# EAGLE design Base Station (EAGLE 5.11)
OC_FARNELL: 1741293

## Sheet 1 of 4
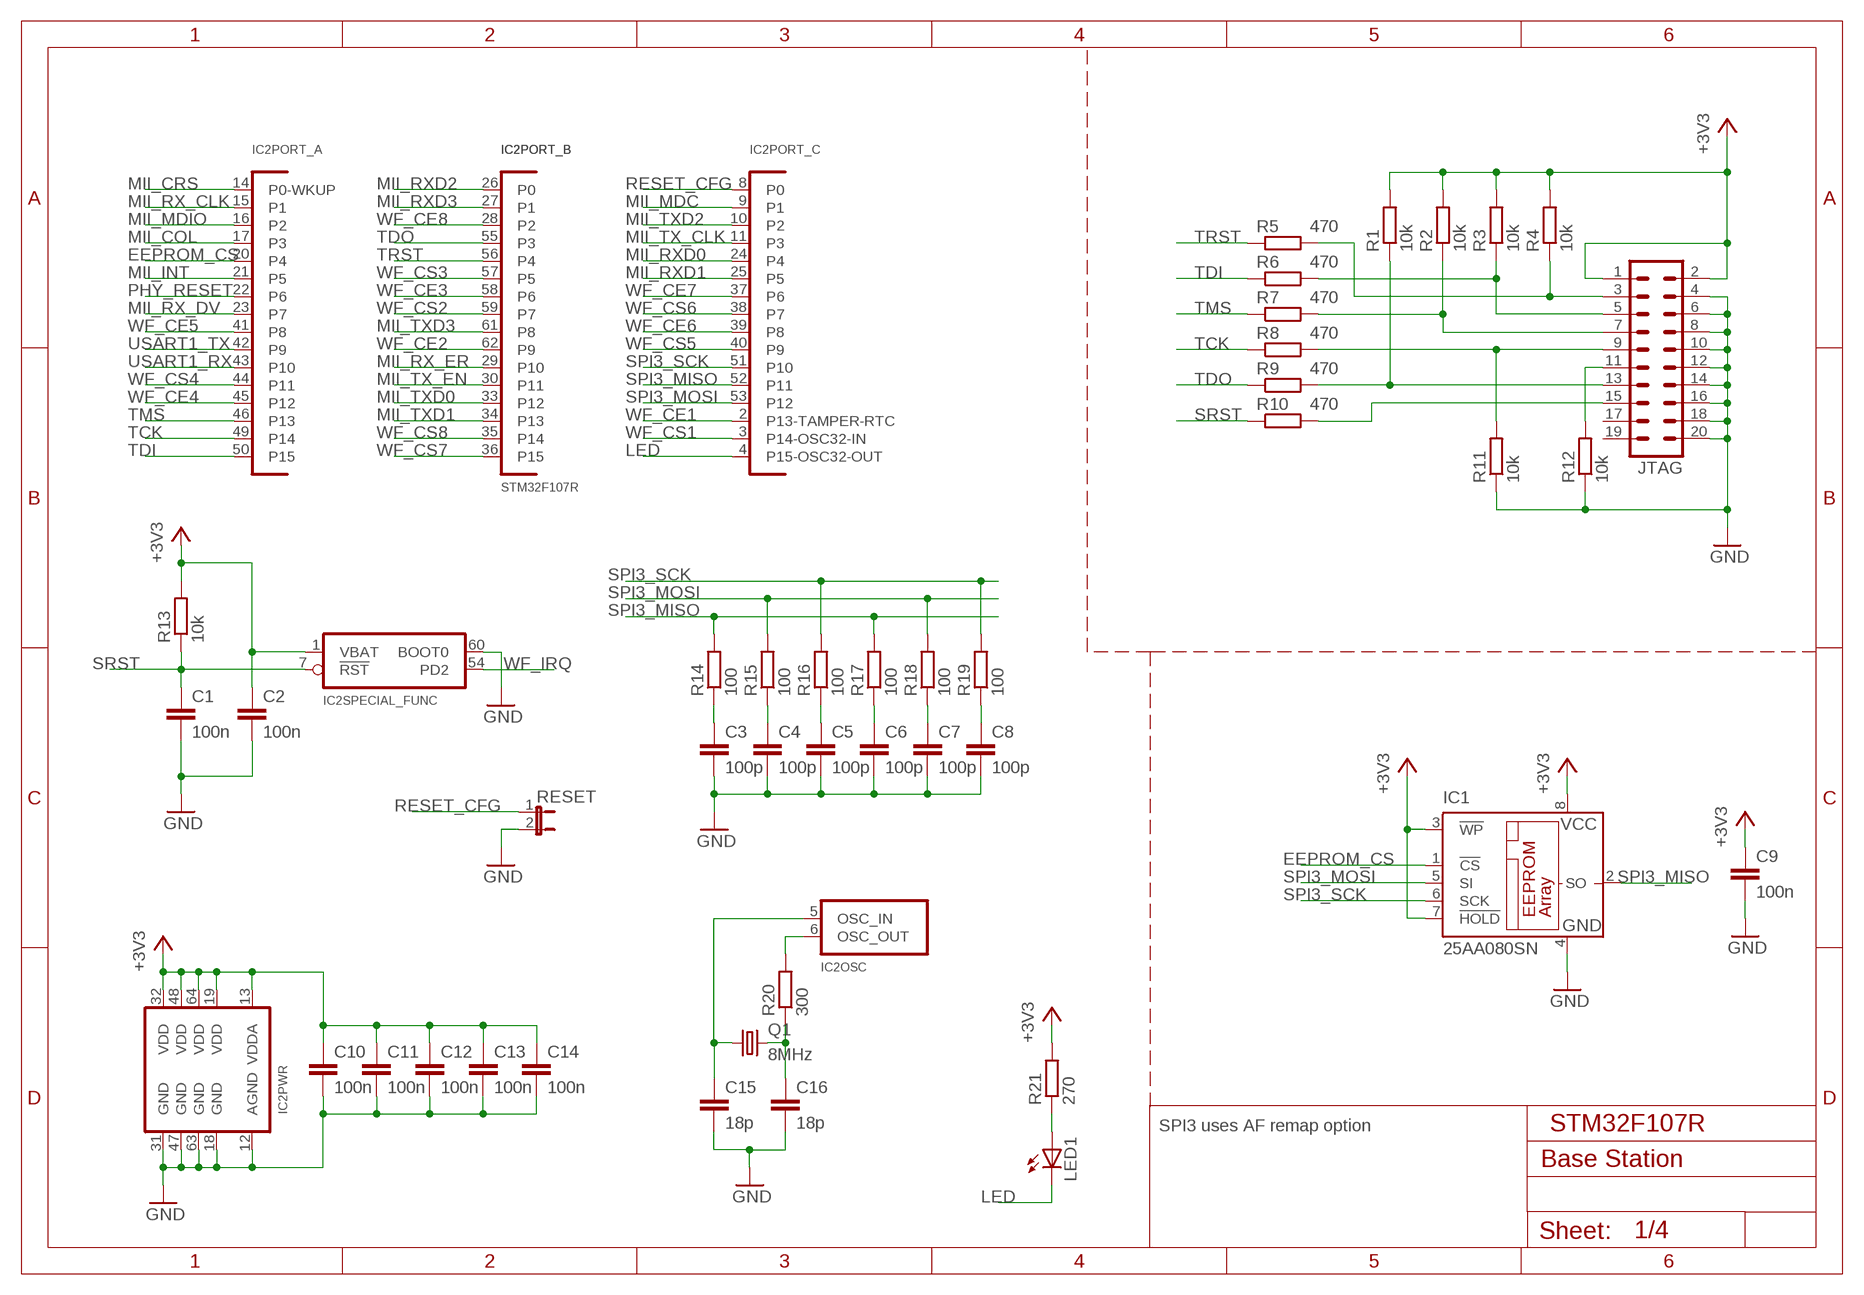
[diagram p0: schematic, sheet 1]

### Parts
C1  100n  C-EUC0805  [C0805]
C2  100n  C-EUC0805  [C0805]
C3  100p  C-EUC0805  [C0805]
C4  100p  C-EUC0805  [C0805]
C5  100p  C-EUC0805  [C0805]
C6  100p  C-EUC0805  [C0805]
C7  100p  C-EUC0805  [C0805]
C8  100p  C-EUC0805  [C0805]
C9  100n  C-EUC0805  [C0805]
C10  100n  C-EUC0805  [C0805]
C11  100n  C-EUC0805  [C0805]
C12  100n  C-EUC0805  [C0805]
C13  100n  C-EUC0805  [C0805]
C14  100n  C-EUC0805  [C0805]
C15  18p  C-EUC0805  [C0805]
C16  18p  C-EUC0805  [C0805]
IC1  25AA080SN  [SO-08]
IC2  STM32F107R  [LQFP64]
JTAG  ML20  [ML20]
LED1  LEDCHIP-LED0805  [CHIP-LED0805]
Q1  8MHz  CRYSTAL7A  [CRYSTAL-7A]
R1  10k  R-EU_R0805  [R0805]
R2  10k  R-EU_R0805  [R0805]
R3  10k  R-EU_R0805  [R0805]
R4  10k  R-EU_R0805  [R0805]
R5  470  R-EU_R0805  [R0805]
R6  470  R-EU_R0805  [R0805]
R7  470  R-EU_R0805  [R0805]
R8  470  R-EU_R0805  [R0805]
R9  470  R-EU_R0805  [R0805]
R10  470  R-EU_R0805  [R0805]
R11  10k  R-EU_R0805  [R0805]
R12  10k  R-EU_R0805  [R0805]
R13  10k  R-EU_R0805  [R0805]
R14  100  R-EU_R0805  [R0805]
R15  100  R-EU_R0805  [R0805]
R16  100  R-EU_R0805  [R0805]
R17  100  R-EU_R0805  [R0805]
R18  100  R-EU_R0805  [R0805]
R19  100  R-EU_R0805  [R0805]
R20  300  R-EU_R0805  [R0805]
R21  270  R-EU_R0805  [R0805]
RESET  JP1E  [JP1]

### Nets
+3V3: C2.1 C9.1 C10.1 C11.1 C12.1 C13.1 C14.1 IC1.3(!WP) IC1.7(!HOLD) IC1.8(VCC) IC2.1(SPECIAL_FUNC:VBAT) IC2.13(PWR:VDDA) IC2.19(PWR:VDD) IC2.32(PWR:VDD) IC2.48(PWR:VDD) IC2.64(PWR:VDD) JTAG.1 JTAG.2 R1.2 R2.2 R3.2 R4.2 R13.2 R21.2 ; also sheet 2,3,4
EEPROM_CS: IC1.1(!CS) IC2.20(PORT_A:P4)
GND: C1.2 C2.2 C3.2 C4.2 C5.2 C6.2 C7.2 C8.2 C9.2 C10.2 C11.2 C12.2 C13.2 C14.2 C15.2 C16.2 IC1.4(GND) IC2.12(PWR:AGND) IC2.18(PWR:GND) IC2.31(PWR:GND) IC2.47(PWR:GND) IC2.60(SPECIAL_FUNC:BOOT0) IC2.63(PWR:GND) JTAG.4 JTAG.6 JTAG.8 JTAG.10 JTAG.12 JTAG.14 JTAG.16 JTAG.18 JTAG.20 R11.1 R12.1 RESET.2 ; also sheet 2,3,4
JTAG-SRST: JTAG.15 R10.2
JTAG-TCK: JTAG.9 R8.2 R11.2
JTAG-TDI: JTAG.5 R3.1 R6.2
JTAG-TDO: JTAG.13 R1.1 R9.2
JTAG-TMS: JTAG.7 R2.1 R7.2
JTAG-TRST: JTAG.3 R4.1 R5.2
LED: IC2.4(PORT_C:P15-OSC32-OUT) LED1.C
MII_COL: IC2.17(PORT_A:P3) ; also sheet 2
MII_CRS: IC2.14(PORT_A:P0-WKUP) ; also sheet 2
MII_INT: IC2.21(PORT_A:P5) ; also sheet 2
MII_MDC: IC2.9(PORT_C:P1) ; also sheet 2
MII_MDIO: IC2.16(PORT_A:P2) ; also sheet 2
MII_RX_CLK: IC2.15(PORT_A:P1) ; also sheet 2
MII_RX_DV: IC2.23(PORT_A:P7) ; also sheet 2
MII_RX_ER: IC2.29(PORT_B:P10) ; also sheet 2
MII_RXD0: IC2.24(PORT_C:P4) ; also sheet 2
MII_RXD1: IC2.25(PORT_C:P5) ; also sheet 2
MII_RXD2: IC2.26(PORT_B:P0) ; also sheet 2
MII_RXD3: IC2.27(PORT_B:P1) ; also sheet 2
MII_TX_CLK: IC2.11(PORT_C:P3) ; also sheet 2
MII_TX_EN: IC2.30(PORT_B:P11) ; also sheet 2
MII_TXD0: IC2.33(PORT_B:P12) ; also sheet 2
MII_TXD1: IC2.34(PORT_B:P13) ; also sheet 2
MII_TXD2: IC2.10(PORT_C:P2) ; also sheet 2
MII_TXD3: IC2.61(PORT_B:P8) ; also sheet 2
N$17: C3.1 R14.1
N$19: C4.1 R15.1
N$57: LED1.A R21.1
N$58: C5.1 R16.1
N$59: C6.1 R17.1
N$60: C7.1 R18.1
N$61: C8.1 R19.1
N$165: IC2.6(OSC:OSC_OUT) R20.2
N$168: C15.1 IC2.5(OSC:OSC_IN) Q1.1
N$169: C16.1 Q1.2 R20.1
N$173: JTAG.11 R12.2
PHY_RESET: IC2.22(PORT_A:P6) ; also sheet 2
RESET_CFG: IC2.8(PORT_C:P0) RESET.1
SPI3_MISO: IC1.2(SO) IC2.52(PORT_C:P11) R14.2 R17.2 ; also sheet 3
SPI3_MOSI: IC1.5(SI) IC2.53(PORT_C:P12) R15.2 R18.2 ; also sheet 3
SPI3_SCK: IC1.6(SCK) IC2.51(PORT_C:P10) R16.2 R19.2 ; also sheet 3
SRST: C1.1 IC2.7(SPECIAL_FUNC:!RST) R10.1 R13.1
TCK: IC2.49(PORT_A:P14) R8.1
TDI: IC2.50(PORT_A:P15) R6.1
TDO: IC2.55(PORT_B:P3) R9.1
TMS: IC2.46(PORT_A:P13) R7.1
TRST: IC2.56(PORT_B:P4) R5.1
USART1_RX: IC2.43(PORT_A:P10) ; also sheet 4
USART1_TX: IC2.42(PORT_A:P9) ; also sheet 4
WF_CE1: IC2.2(PORT_C:P13-TAMPER-RTC) ; also sheet 3
WF_CE2: IC2.62(PORT_B:P9) ; also sheet 3
WF_CE3: IC2.58(PORT_B:P6) ; also sheet 3
WF_CE4: IC2.45(PORT_A:P12) ; also sheet 3
WF_CE5: IC2.41(PORT_A:P8) ; also sheet 3
WF_CE6: IC2.39(PORT_C:P8) ; also sheet 3
WF_CE7: IC2.37(PORT_C:P6) ; also sheet 3
WF_CE8: IC2.28(PORT_B:P2) ; also sheet 3
WF_CS1: IC2.3(PORT_C:P14-OSC32-IN) ; also sheet 3
WF_CS2: IC2.59(PORT_B:P7) ; also sheet 3
WF_CS3: IC2.57(PORT_B:P5) ; also sheet 3
WF_CS4: IC2.44(PORT_A:P11) ; also sheet 3
WF_CS5: IC2.40(PORT_C:P9) ; also sheet 3
WF_CS6: IC2.38(PORT_C:P7) ; also sheet 3
WF_CS7: IC2.36(PORT_B:P15) ; also sheet 3
WF_CS8: IC2.35(PORT_B:P14) ; also sheet 3
WF_IRQ: IC2.54(SPECIAL_FUNC:PD2) ; also sheet 3
Unconnected: JTAG.17 JTAG.19

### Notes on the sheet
- SPI3 uses AF remap option | STM32F107R

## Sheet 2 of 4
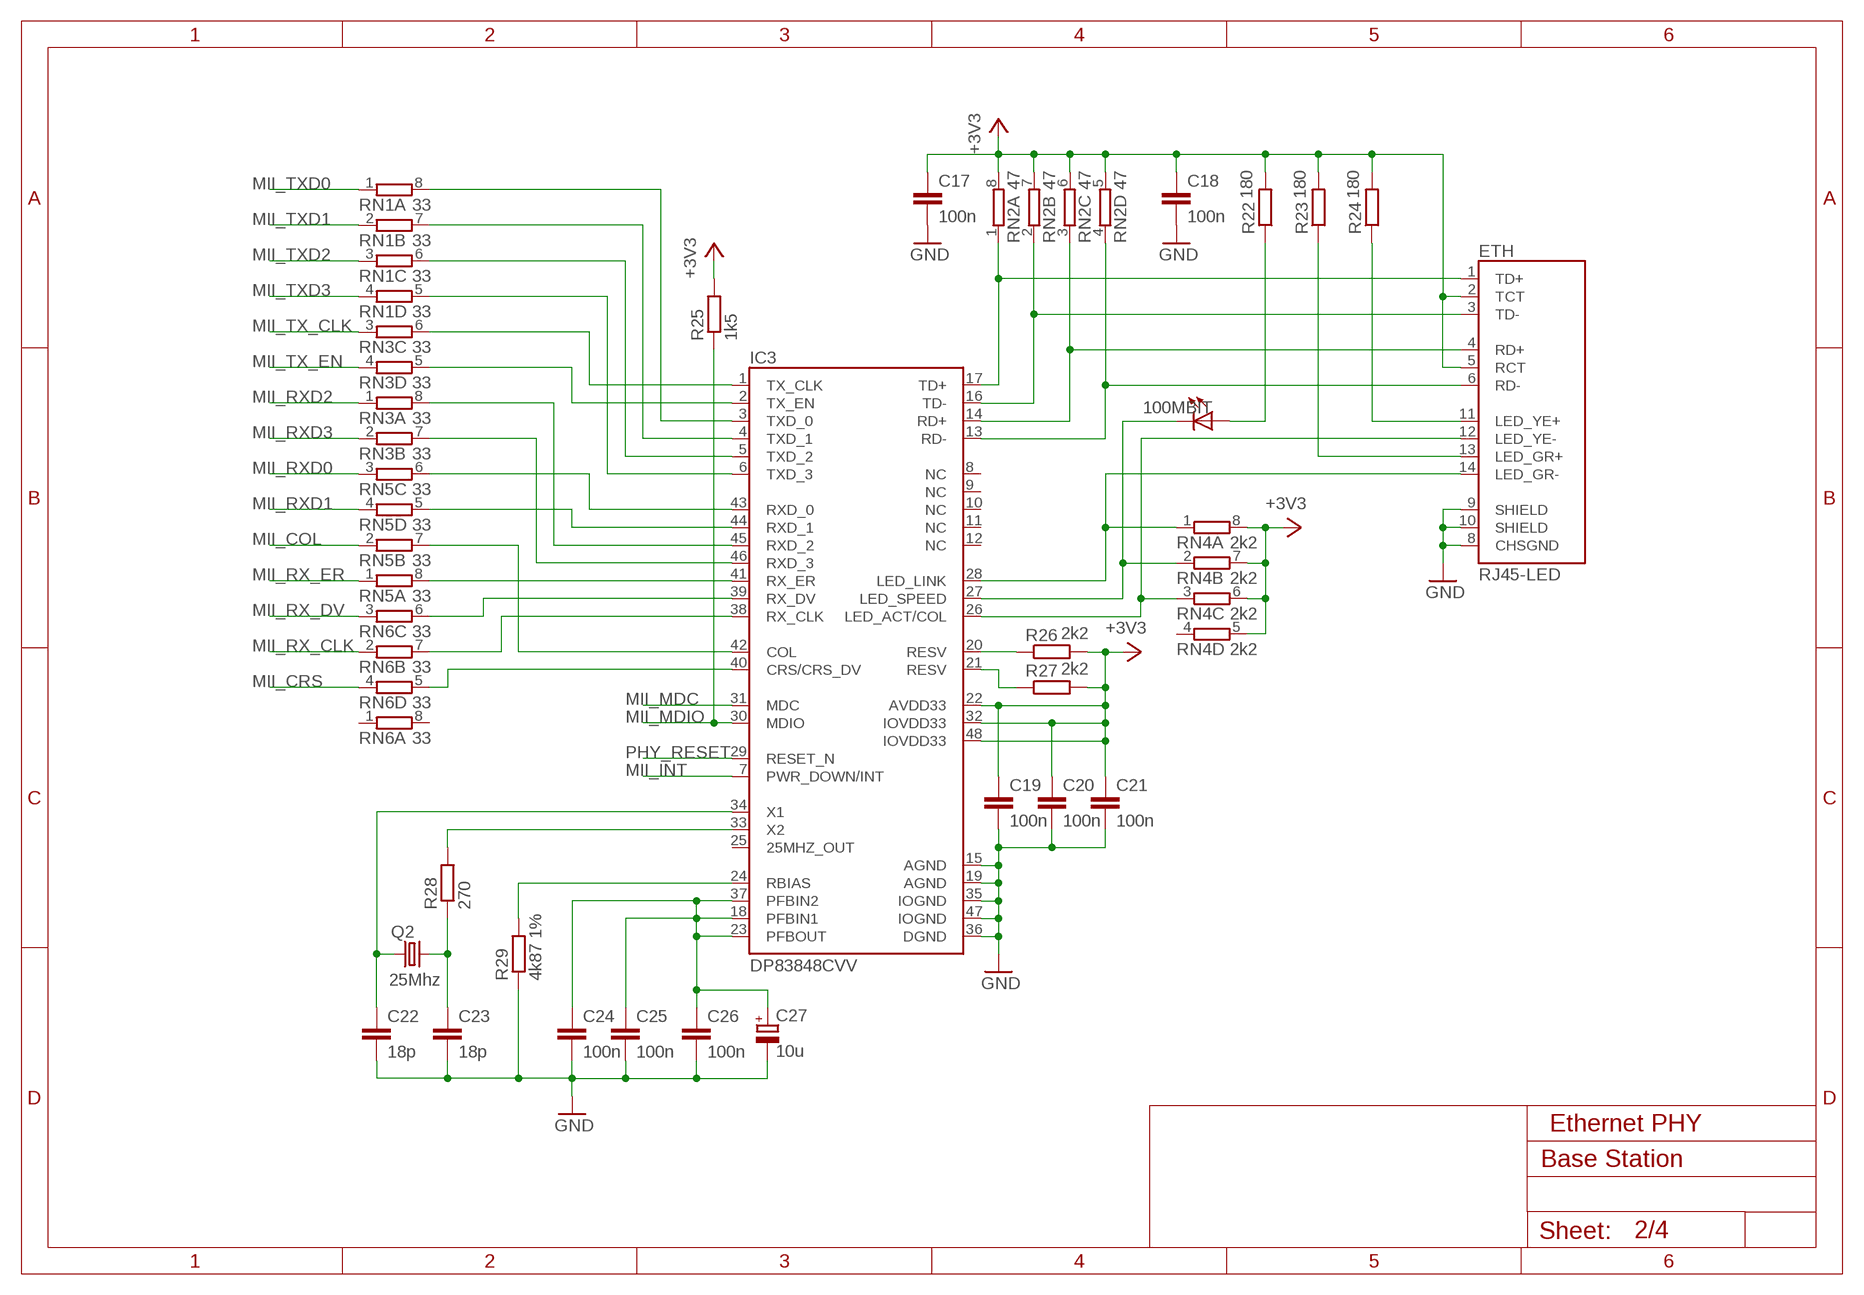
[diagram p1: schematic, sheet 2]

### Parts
100MBIT  LEDCHIP-LED0805  [CHIP-LED0805]
C17  100n  C-EUC0805  [C0805]
C18  100n  C-EUC0805  [C0805]
C19  100n  C-EUC0805  [C0805]
C20  100n  C-EUC0805  [C0805]
C21  100n  C-EUC0805  [C0805]
C22  18p  C-EUC0805  [C0805]
C23  18p  C-EUC0805  [C0805]
C24  100n  C-EUC0805  [C0805]
C25  100n  C-EUC0805  [C0805]
C26  100n  C-EUC0805  [C0805]
C27  10u  CPOL-EUC/6032-28R  [C/6032-28R]
ETH  RJ45-LED  [RJ45-LED]
IC3  DP83848CVV  DB8348C  [LQFP48]
Q2  25Mhz  CRYSTALCTS406  [CTS406]
R22  180  R-EU_R0805  [R0805]
R23  180  R-EU_R0805  [R0805]
R24  180  R-EU_R0805  [R0805]
R25  1k5  R-EU_R0805  [R0805]
R26  2k2  R-EU_R0805  [R0805]
R27  2k2  R-EU_R0805  [R0805]
R28  270  R-EU_R0805  [R0805]
R29  4k87 1%  R-EU_R0805  [R0805]
RN1  33  4R-NCAY16  [CAY16]
RN2  47  4R-NCAY16  [CAY16]
RN3  33  4R-NCAY16  [CAY16]
RN4  2k2  4R-NCAY16  [CAY16]
RN5  33  4R-NCAY16  [CAY16]
RN6  33  4R-NCAY16  [CAY16]

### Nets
+3V3: C17.1 C18.1 C19.1 C20.1 C21.1 ETH.2(TCT) ETH.5(RCT) IC3.22(AVDD33) IC3.32(IOVDD33) IC3.48(IOVDD33) R22.2 R23.2 R24.2 R25.2 R26.2 R27.2 RN2.5 RN2.6 RN2.7 RN2.8 RN4.5 RN4.6 RN4.7 RN4.8 ; also sheet 1,3,4
GND: C17.2 C18.2 C19.2 C20.2 C21.2 C22.2 C23.2 C24.2 C25.2 C26.2 C27.- ETH.8(CHSGND) ETH.9(SHIELD) ETH.10(SHIELD) IC3.15(AGND) IC3.19(AGND) IC3.35(IOGND) IC3.36(DGND) IC3.47(IOGND) R29.1 ; also sheet 1,3,4
MII_COL: RN5.2 ; also sheet 1
MII_CRS: RN6.4 ; also sheet 1
MII_INT: IC3.7(PWR_DOWN/INT) ; also sheet 1
MII_MDC: IC3.31(MDC) ; also sheet 1
MII_MDIO: IC3.30(MDIO) R25.1 ; also sheet 1
MII_RX_CLK: RN6.2 ; also sheet 1
MII_RX_DV: RN6.3 ; also sheet 1
MII_RX_ER: RN5.1 ; also sheet 1
MII_RXD0: RN5.3 ; also sheet 1
MII_RXD1: RN5.4 ; also sheet 1
MII_RXD2: RN3.1 ; also sheet 1
MII_RXD3: RN3.2 ; also sheet 1
MII_TX_CLK: RN3.3 ; also sheet 1
MII_TX_EN: RN3.4 ; also sheet 1
MII_TXD0: RN1.1 ; also sheet 1
MII_TXD1: RN1.2 ; also sheet 1
MII_TXD2: RN1.3 ; also sheet 1
MII_TXD3: RN1.4 ; also sheet 1
N$1: IC3.3(TXD_0) RN1.8
N$2: IC3.4(TXD_1) RN1.7
N$3: IC3.5(TXD_2) RN1.6
N$4: IC3.6(TXD_3) RN1.5
N$5: IC3.1(TX_CLK) RN3.6
N$6: IC3.2(TX_EN) RN3.5
N$7: IC3.45(RXD_2) RN3.8
N$8: IC3.46(RXD_3) RN3.7
N$9: IC3.43(RXD_0) RN5.6
N$10: IC3.44(RXD_1) RN5.5
N$11: IC3.42(COL) RN5.7
N$12: IC3.41(RX_ER) RN5.8
N$13: IC3.39(RX_DV) RN6.6
N$14: IC3.38(RX_CLK) RN6.7
N$15: IC3.40(CRS/CRS_DV) RN6.5
N$16: IC3.20(RESV) R26.1
N$18: C23.1 Q2.3 R28.1
N$20: IC3.24(RBIAS) R29.2
N$21: C24.1 C25.1 C26.1 C27.+ IC3.18(PFBIN1) IC3.23(PFBOUT) IC3.37(PFBIN2)
N$22: IC3.21(RESV) R27.1
N$23: ETH.12(LED_YE-) IC3.26(LED_ACT/COL) RN4.3
N$24: 100MBIT.C IC3.27(LED_SPEED) RN4.2
N$25: ETH.14(LED_GR-) IC3.28(LED_LINK) RN4.1
N$26: ETH.6(RD-) IC3.13(RD-) RN2.4
N$27: ETH.4(RD+) IC3.14(RD+) RN2.3
N$28: ETH.3(TD-) IC3.16(TD-) RN2.2
N$29: ETH.1(TD+) IC3.17(TD+) RN2.1
N$31: ETH.11(LED_YE+) R24.1
N$32: ETH.13(LED_GR+) R23.1
N$33: 100MBIT.A R22.1
PHY_RESET: IC3.29(RESET_N) ; also sheet 1
X1: C22.1 IC3.34(X1) Q2.1
X2: IC3.33(X2) R28.2
Unconnected: IC3.8(NC) IC3.9(NC) IC3.10(NC) IC3.11(NC) IC3.12(NC) IC3.25(25MHZ_OUT) RN4.4 RN6.1 RN6.8

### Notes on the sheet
- Ethernet PHY

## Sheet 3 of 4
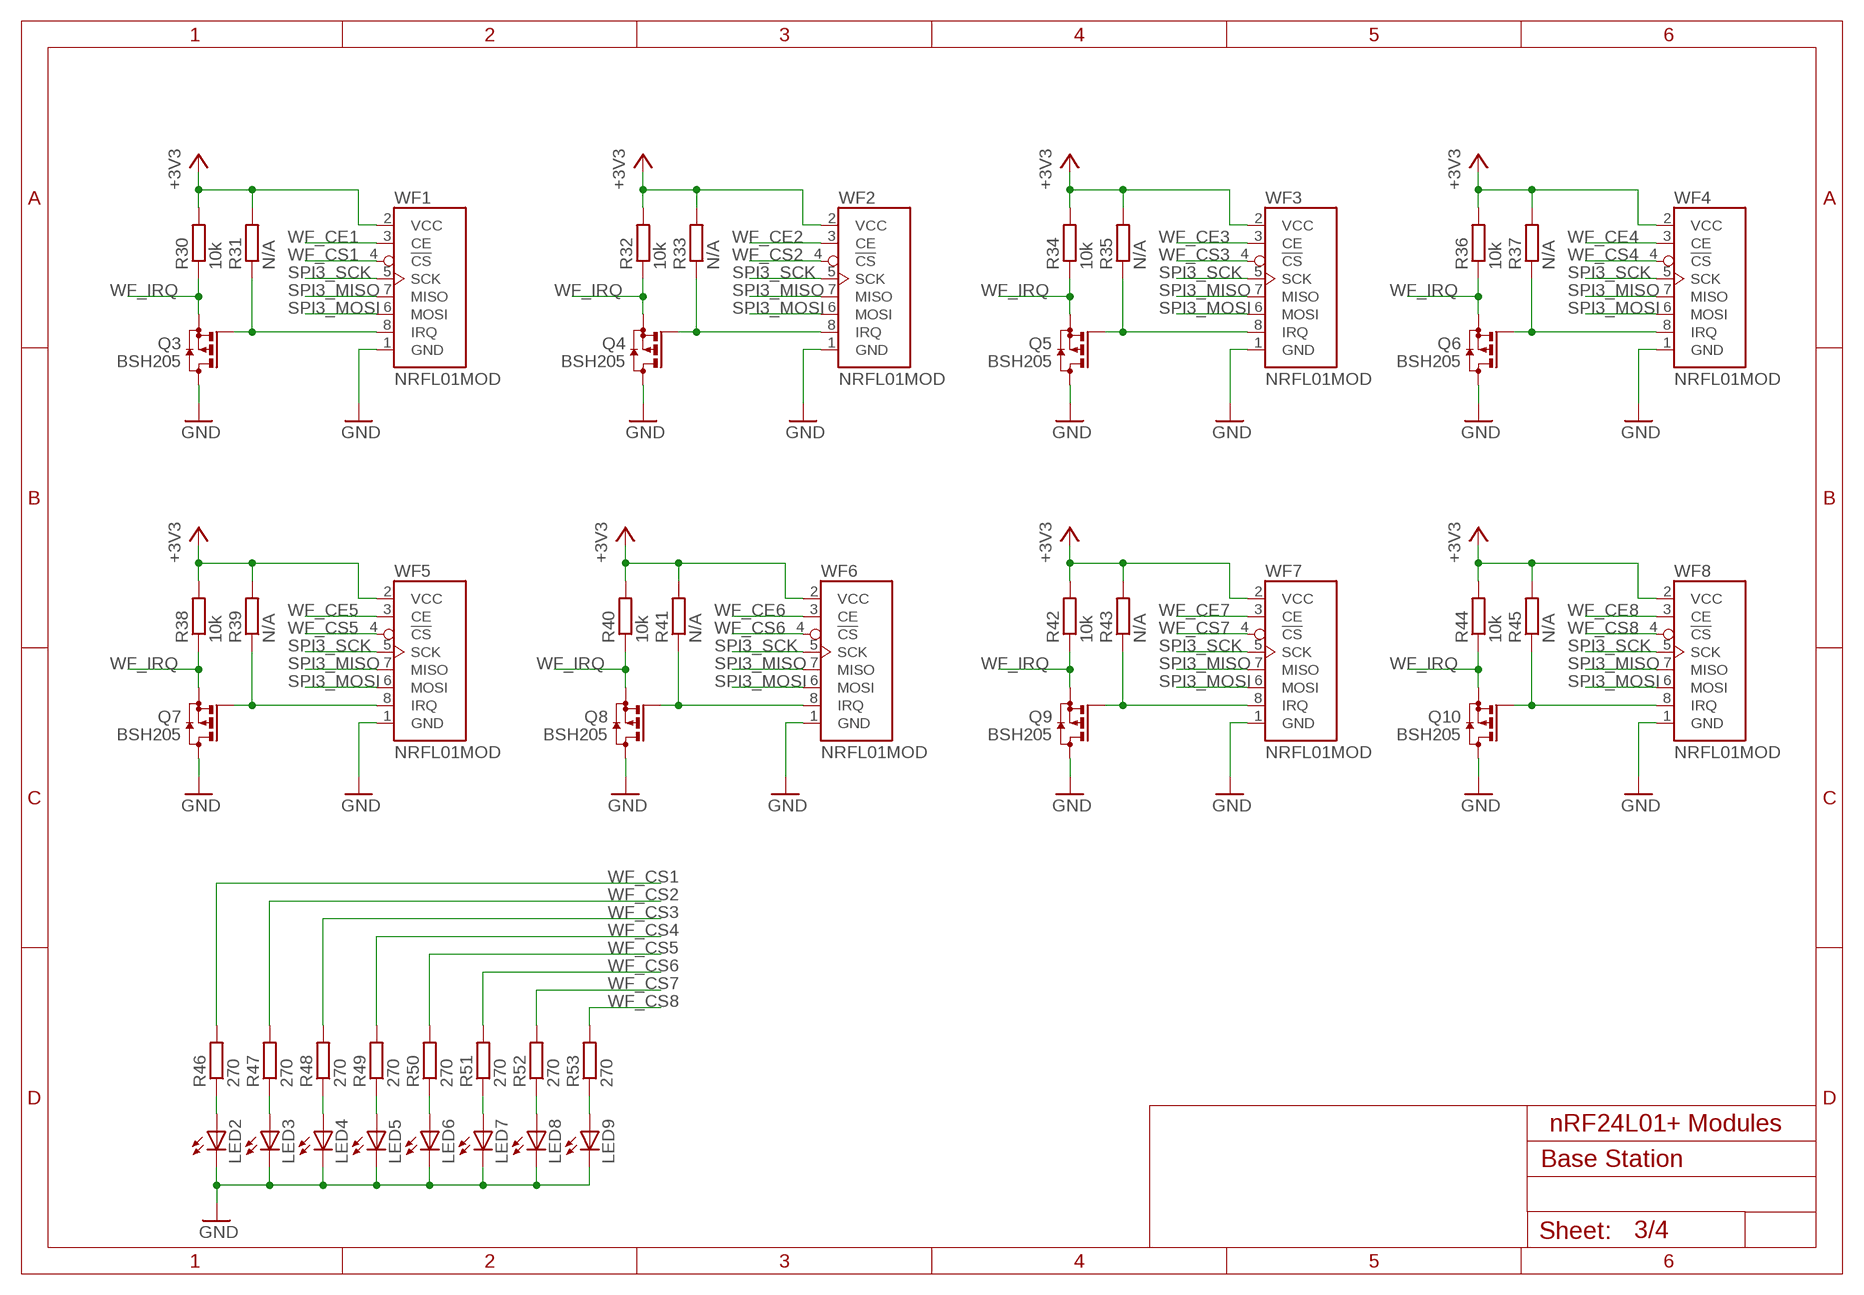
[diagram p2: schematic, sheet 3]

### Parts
LED2  LEDCHIP-LED0805  [CHIP-LED0805]
LED3  LEDCHIP-LED0805  [CHIP-LED0805]
LED4  LEDCHIP-LED0805  [CHIP-LED0805]
LED5  LEDCHIP-LED0805  [CHIP-LED0805]
LED6  LEDCHIP-LED0805  [CHIP-LED0805]
LED7  LEDCHIP-LED0805  [CHIP-LED0805]
LED8  LEDCHIP-LED0805  [CHIP-LED0805]
LED9  LEDCHIP-LED0805  [CHIP-LED0805]
Q3  BSH205  BSS84  [SOT23]
Q4  BSH205  BSS84  [SOT23]
Q5  BSH205  BSS84  [SOT23]
Q6  BSH205  BSS84  [SOT23]
Q7  BSH205  BSS84  [SOT23]
Q8  BSH205  BSS84  [SOT23]
Q9  BSH205  BSS84  [SOT23]
Q10  BSH205  BSS84  [SOT23]
R30  10k  R-EU_R0805  [R0805]
R31  N/A  R-EU_R0805  [R0805]
R32  10k  R-EU_R0805  [R0805]
R33  N/A  R-EU_R0805  [R0805]
R34  10k  R-EU_R0805  [R0805]
R35  N/A  R-EU_R0805  [R0805]
R36  10k  R-EU_R0805  [R0805]
R37  N/A  R-EU_R0805  [R0805]
R38  10k  R-EU_R0805  [R0805]
R39  N/A  R-EU_R0805  [R0805]
R40  10k  R-EU_R0805  [R0805]
R41  N/A  R-EU_R0805  [R0805]
R42  10k  R-EU_R0805  [R0805]
R43  N/A  R-EU_R0805  [R0805]
R44  10k  R-EU_R0805  [R0805]
R45  N/A  R-EU_R0805  [R0805]
R46  270  R-EU_R0805  [R0805]
R47  270  R-EU_R0805  [R0805]
R48  270  R-EU_R0805  [R0805]
R49  270  R-EU_R0805  [R0805]
R50  270  R-EU_R0805  [R0805]
R51  270  R-EU_R0805  [R0805]
R52  270  R-EU_R0805  [R0805]
R53  270  R-EU_R0805  [R0805]
WF1  NRFL01MOD  [NRF24L01MOD]
WF2  NRFL01MOD  [NRF24L01MOD]
WF3  NRFL01MOD  [NRF24L01MOD]
WF4  NRFL01MOD  [NRF24L01MOD]
WF5  NRFL01MOD  [NRF24L01MOD]
WF6  NRFL01MOD  [NRF24L01MOD]
WF7  NRFL01MOD  [NRF24L01MOD]
WF8  NRFL01MOD  [NRF24L01MOD]

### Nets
+3V3: R30.2 R31.2 R32.2 R33.2 R34.2 R35.2 R36.2 R37.2 R38.2 R39.2 R40.2 R41.2 R42.2 R43.2 R44.2 R45.2 WF1.2(VCC) WF2.2(VCC) WF3.2(VCC) WF4.2(VCC) WF5.2(VCC) WF6.2(VCC) WF7.2(VCC) WF8.2(VCC) ; also sheet 1,2,4
GND: LED2.C LED3.C LED4.C LED5.C LED6.C LED7.C LED8.C LED9.C Q3.3(D) Q4.3(D) Q5.3(D) Q6.3(D) Q7.3(D) Q8.3(D) Q9.3(D) Q10.3(D) WF1.1(GND) WF2.1(GND) WF3.1(GND) WF4.1(GND) WF5.1(GND) WF6.1(GND) WF7.1(GND) WF8.1(GND) ; also sheet 1,2,4
N$30: Q3.1(G) R31.1 WF1.8(IRQ)
N$34: Q4.1(G) R33.1 WF2.8(IRQ)
N$35: Q5.1(G) R35.1 WF3.8(IRQ)
N$36: Q6.1(G) R37.1 WF4.8(IRQ)
N$37: Q7.1(G) R39.1 WF5.8(IRQ)
N$38: Q8.1(G) R41.1 WF6.8(IRQ)
N$39: Q9.1(G) R43.1 WF7.8(IRQ)
N$40: Q10.1(G) R45.1 WF8.8(IRQ)
N$49: LED2.A R46.1
N$50: LED3.A R47.1
N$51: LED4.A R48.1
N$52: LED5.A R49.1
N$53: LED6.A R50.1
N$54: LED7.A R51.1
N$55: LED8.A R52.1
N$56: LED9.A R53.1
SPI3_MISO: WF1.7(MISO) WF2.7(MISO) WF3.7(MISO) WF4.7(MISO) WF5.7(MISO) WF6.7(MISO) WF7.7(MISO) WF8.7(MISO) ; also sheet 1
SPI3_MOSI: WF1.6(MOSI) WF2.6(MOSI) WF3.6(MOSI) WF4.6(MOSI) WF5.6(MOSI) WF6.6(MOSI) WF7.6(MOSI) WF8.6(MOSI) ; also sheet 1
SPI3_SCK: WF1.5(SCK) WF2.5(SCK) WF3.5(SCK) WF4.5(SCK) WF5.5(SCK) WF6.5(SCK) WF7.5(SCK) WF8.5(SCK) ; also sheet 1
WF_CE1: WF1.3(CE) ; also sheet 1
WF_CE2: WF2.3(CE) ; also sheet 1
WF_CE3: WF3.3(CE) ; also sheet 1
WF_CE4: WF4.3(CE) ; also sheet 1
WF_CE5: WF5.3(CE) ; also sheet 1
WF_CE6: WF6.3(CE) ; also sheet 1
WF_CE7: WF7.3(CE) ; also sheet 1
WF_CE8: WF8.3(CE) ; also sheet 1
WF_CS1: R46.2 WF1.4(!CS) ; also sheet 1
WF_CS2: R47.2 WF2.4(!CS) ; also sheet 1
WF_CS3: R48.2 WF3.4(!CS) ; also sheet 1
WF_CS4: R49.2 WF4.4(!CS) ; also sheet 1
WF_CS5: R50.2 WF5.4(!CS) ; also sheet 1
WF_CS6: R51.2 WF6.4(!CS) ; also sheet 1
WF_CS7: R52.2 WF7.4(!CS) ; also sheet 1
WF_CS8: R53.2 WF8.4(!CS) ; also sheet 1
WF_IRQ: Q3.2(S) Q4.2(S) Q5.2(S) Q6.2(S) Q7.2(S) Q8.2(S) Q9.2(S) Q10.2(S) R30.1 R32.1 R34.1 R36.1 R38.1 R40.1 R42.1 R44.1 ; also sheet 1

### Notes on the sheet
- nRF24L01+ Modules

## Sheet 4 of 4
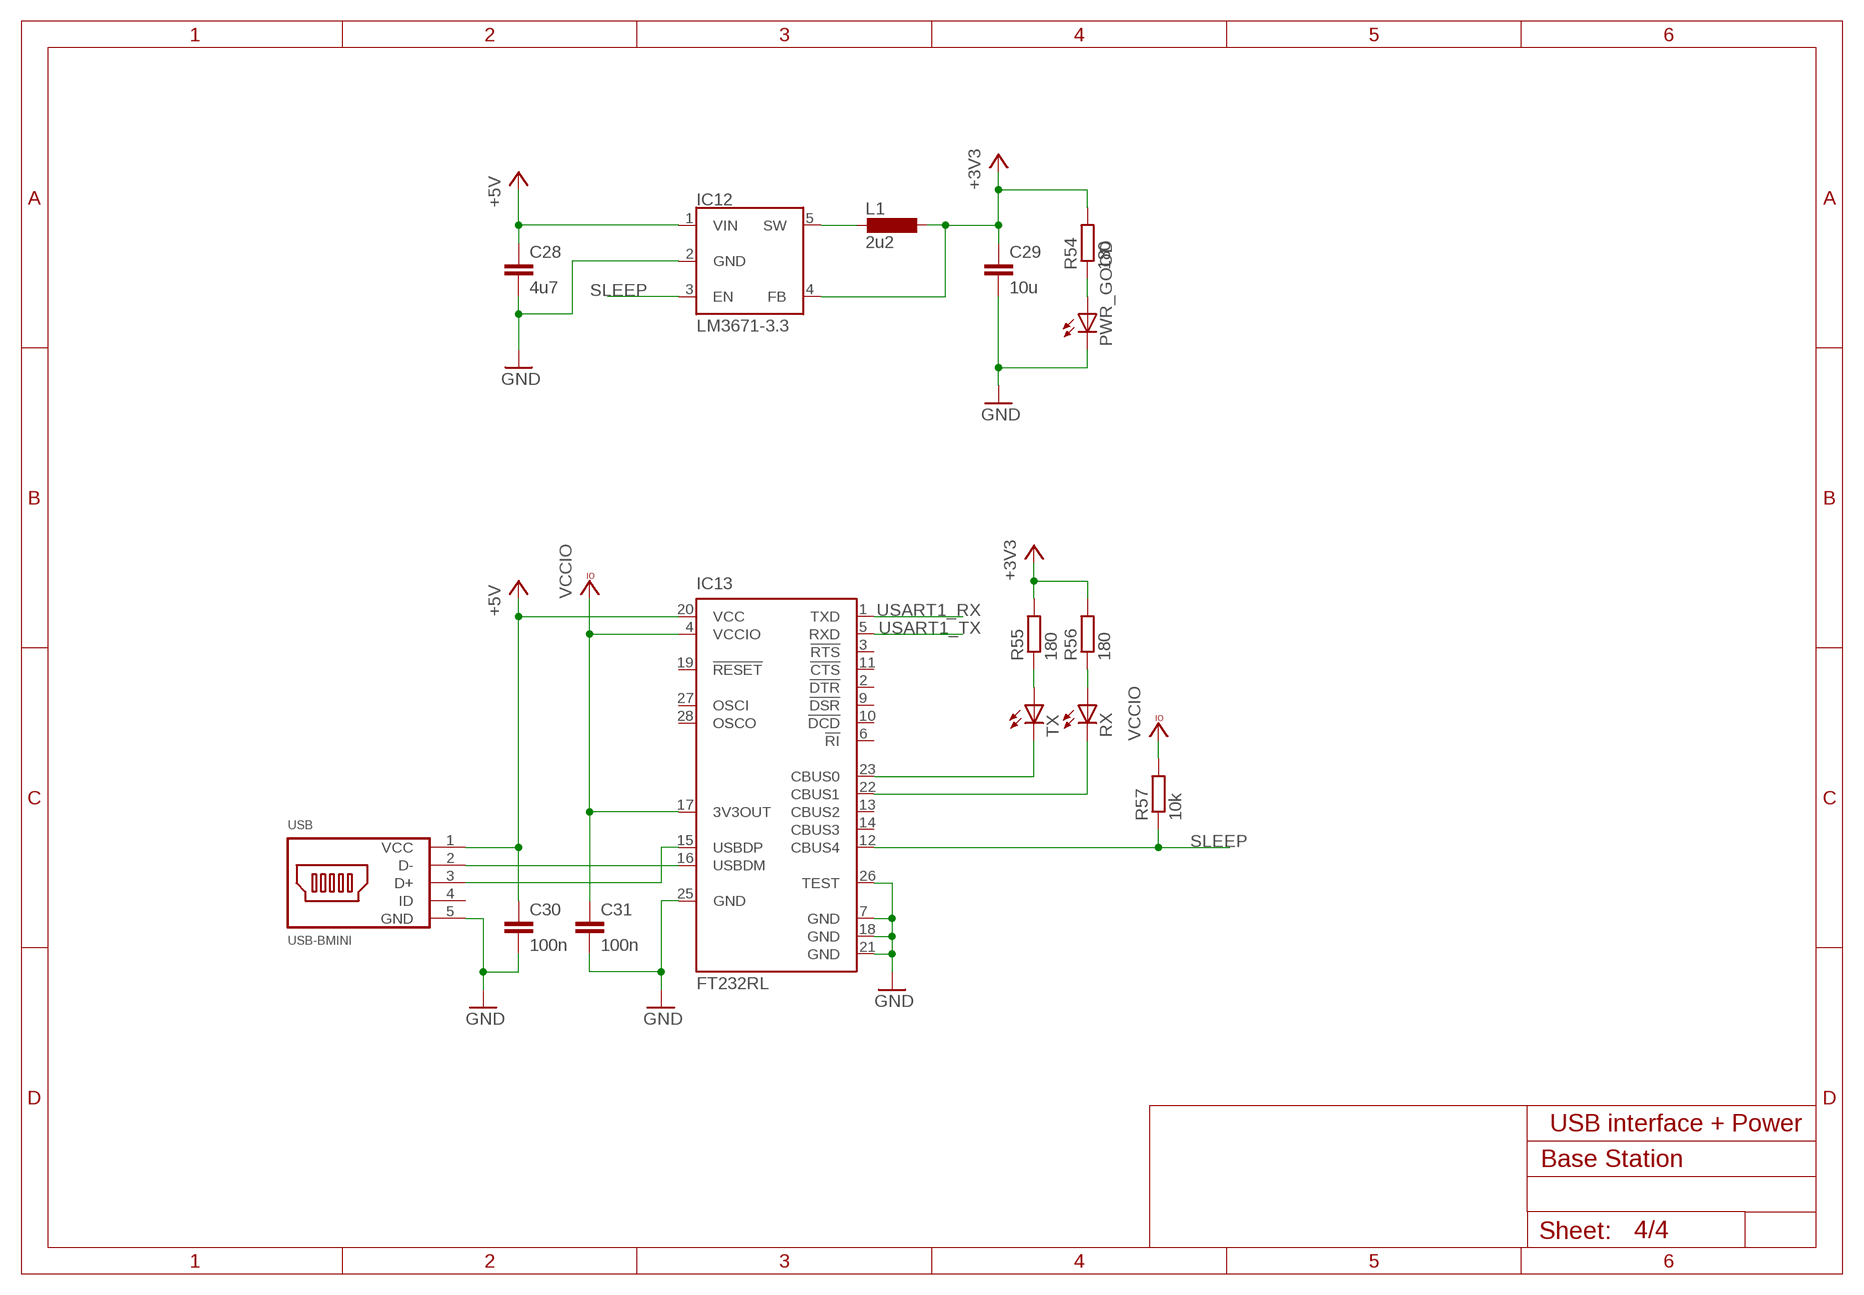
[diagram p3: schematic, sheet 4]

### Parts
C28  4u7  C-EUC0805  [C0805]
C29  10u  C-EUC0805  [C0805]
C30  100n  C-EUC0805  [C0805]
C31  100n  C-EUC0805  [C0805]
IC12  LM3671-3.3  LM3671  [SOT23-5]
IC13  FT232RL  [SSOP28]
L1  2u2  LIHLP  [IHLP1616]
PWR_GOOD  LEDCHIP-LED0805  [CHIP-LED0805]
R54  180  R-EU_R0805  [R0805]
R55  180  R-EU_R0805  [R0805]
R56  180  R-EU_R0805  [R0805]
R57  10k  R-EU_R0805  [R0805]
RX  LEDCHIP-LED0805  [CHIP-LED0805]
TX  LEDCHIP-LED0805  [CHIP-LED0805]
USB  USB-BMINI  [USB-BMINI]

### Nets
+3V3: C29.1 IC12.4(FB) L1.P$1 R54.2 R55.2 R56.2 ; also sheet 1,2,3
+5V: C28.1 C30.1 IC12.1(VIN) IC13.20(VCC) USB.1(VCC)
GND: C28.2 C29.2 C30.2 C31.2 IC12.2(GND) IC13.7(GND) IC13.18(GND) IC13.21(GND) IC13.25(GND) IC13.26(TEST) PWR_GOOD.C USB.5(GND) ; also sheet 1,2,3
N$41: IC13.16(USBDM) USB.2(D-)
N$42: IC13.15(USBDP) USB.3(D+)
N$43: IC13.23(CBUS0) TX.C
N$44: IC13.22(CBUS1) RX.C
N$45: IC12.5(SW) L1.P$2
N$46: R55.1 TX.A
N$47: R56.1 RX.A
N$48: PWR_GOOD.A R54.1
SLEEP: IC12.3(EN) IC13.12(CBUS4) R57.1
USART1_RX: IC13.1(TXD) ; also sheet 1
USART1_TX: IC13.5(RXD) ; also sheet 1
VCCIO: C31.1 IC13.4(VCCIO) IC13.17(3V3OUT) R57.2
Unconnected: IC13.2(!DTR) IC13.3(!RTS) IC13.6(!RI) IC13.9(!DSR) IC13.10(!DCD) IC13.11(!CTS) IC13.13(CBUS2) IC13.14(CBUS3) IC13.19(!RESET) IC13.27(OSCI) IC13.28(OSCO) USB.4(ID)

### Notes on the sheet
- USB interface + Power

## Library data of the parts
100MBIT LED1-LED9 PWR_GOOD RX TX = led:LED: LED
C1-C26 C28-C31 = rcl:C-EU: CAPACITOR, European symbol
C27 = rcl:CPOL-EU: POLARIZED CAPACITOR, European symbol
ETH = Marvin:RJ45-LED
IC1 = microchip:25*: Serial EEPROM 4K/ 8K , SPI bus; MF: MICROCHIP; MPN: 25AA080/SN; OC_FARNELL: 1816072; OC_NEWARK: 92C7351
IC2 = Marvin:STM32F107
IC3 = Marvin:DB8348C
IC12 = Marvin:LM3671
IC13 = ftdichip:FT232R: Source: http://www.ftdichip.com/Documents/DataSheets/DS_FT232R_v104.pdf; MPN: FT232RL; OC_FARNELL: 1146032; OC_NEWARK: 91K9918
JTAG = con-harting-ml:ML20: HARTING
L1 = Marvin:L
Q1 = Marvin:CRYSTAL
Q2 = crystal:CRYSTAL: CRYSTAL; OC_FARNELL: unknown; OC_NEWARK: unknown
Q3-Q10 = transistor-small-signal:BSS84: P-CHANNEL MOS FET
R1-R57 = rcl:R-EU_: RESISTOR, European symbol
RESET = jumper:JP1E: JUMPER
RN1-RN6 = resistor-dil:4R-N: Array Chip Resistor Source: RS Component / Phycomp; OC_FARNELL: unknown; OC_NEWARK: unknown
USB = Marvin:USB-BMINI
WF1-WF8 = Marvin:NRFL01MOD

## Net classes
0 default: width 0.152 mm, clearance 0.152 mm

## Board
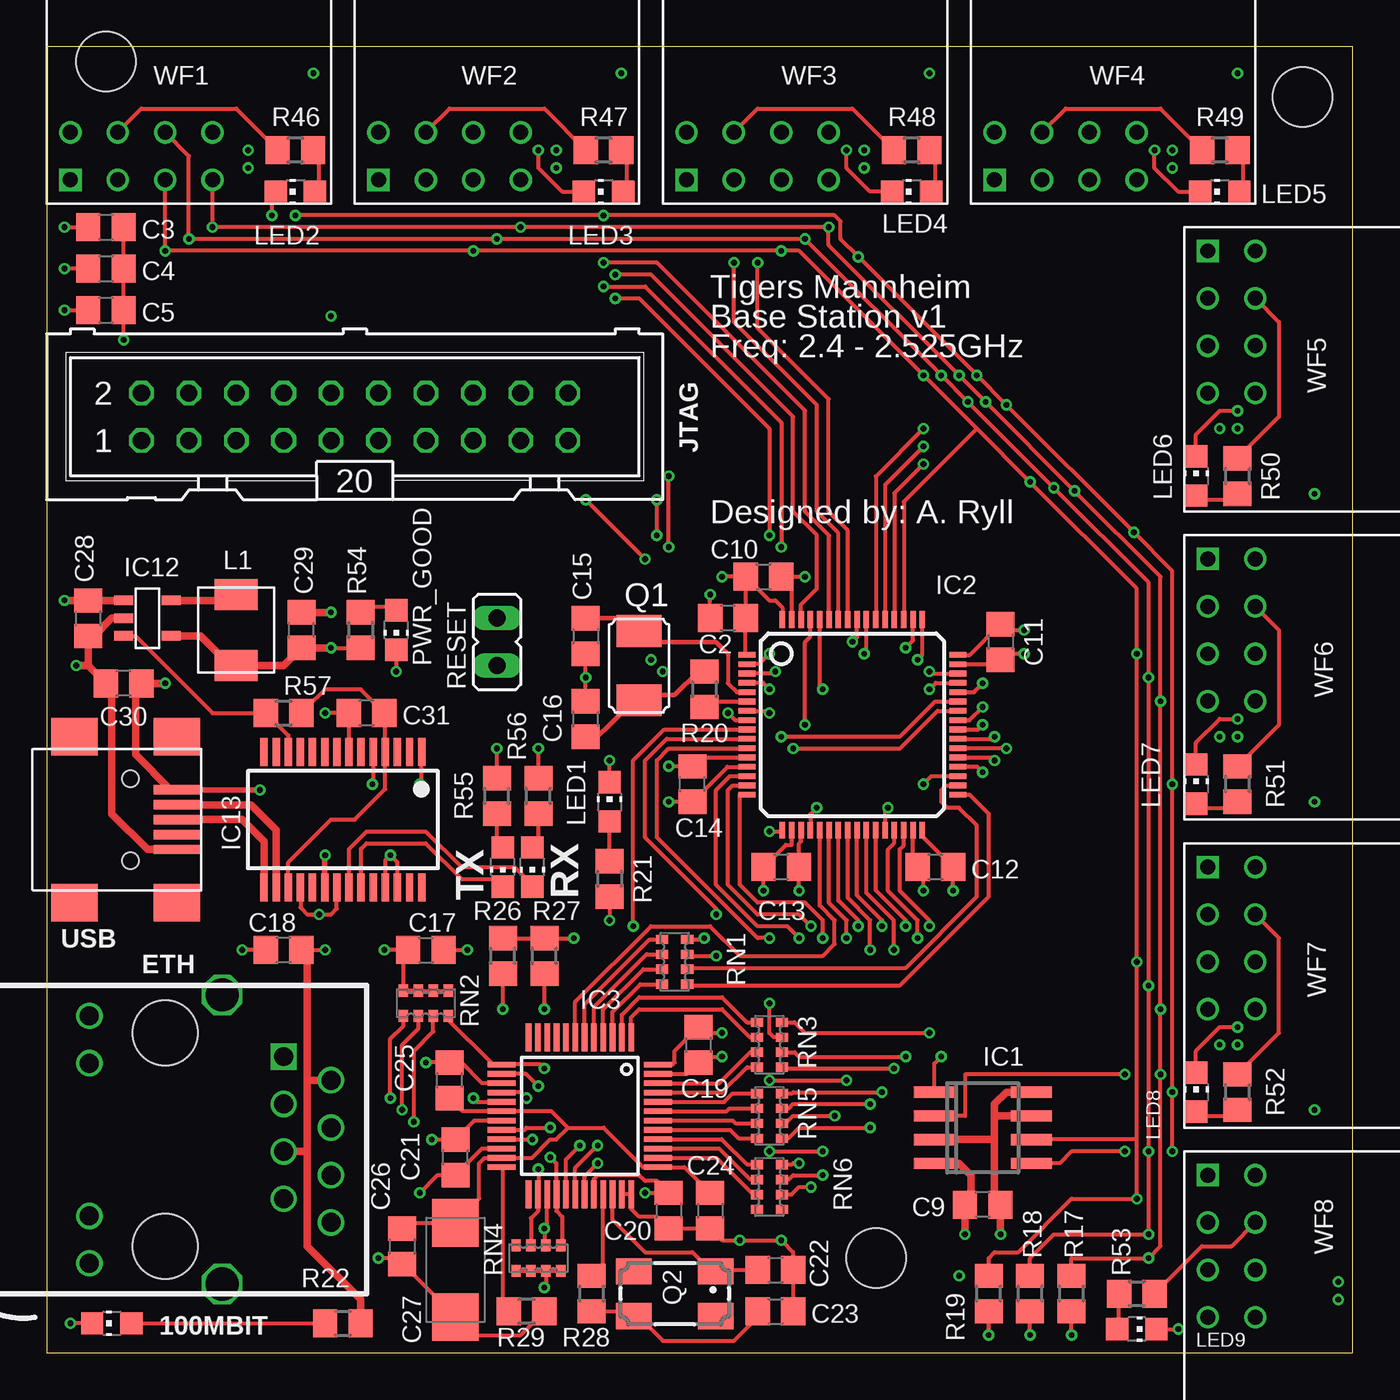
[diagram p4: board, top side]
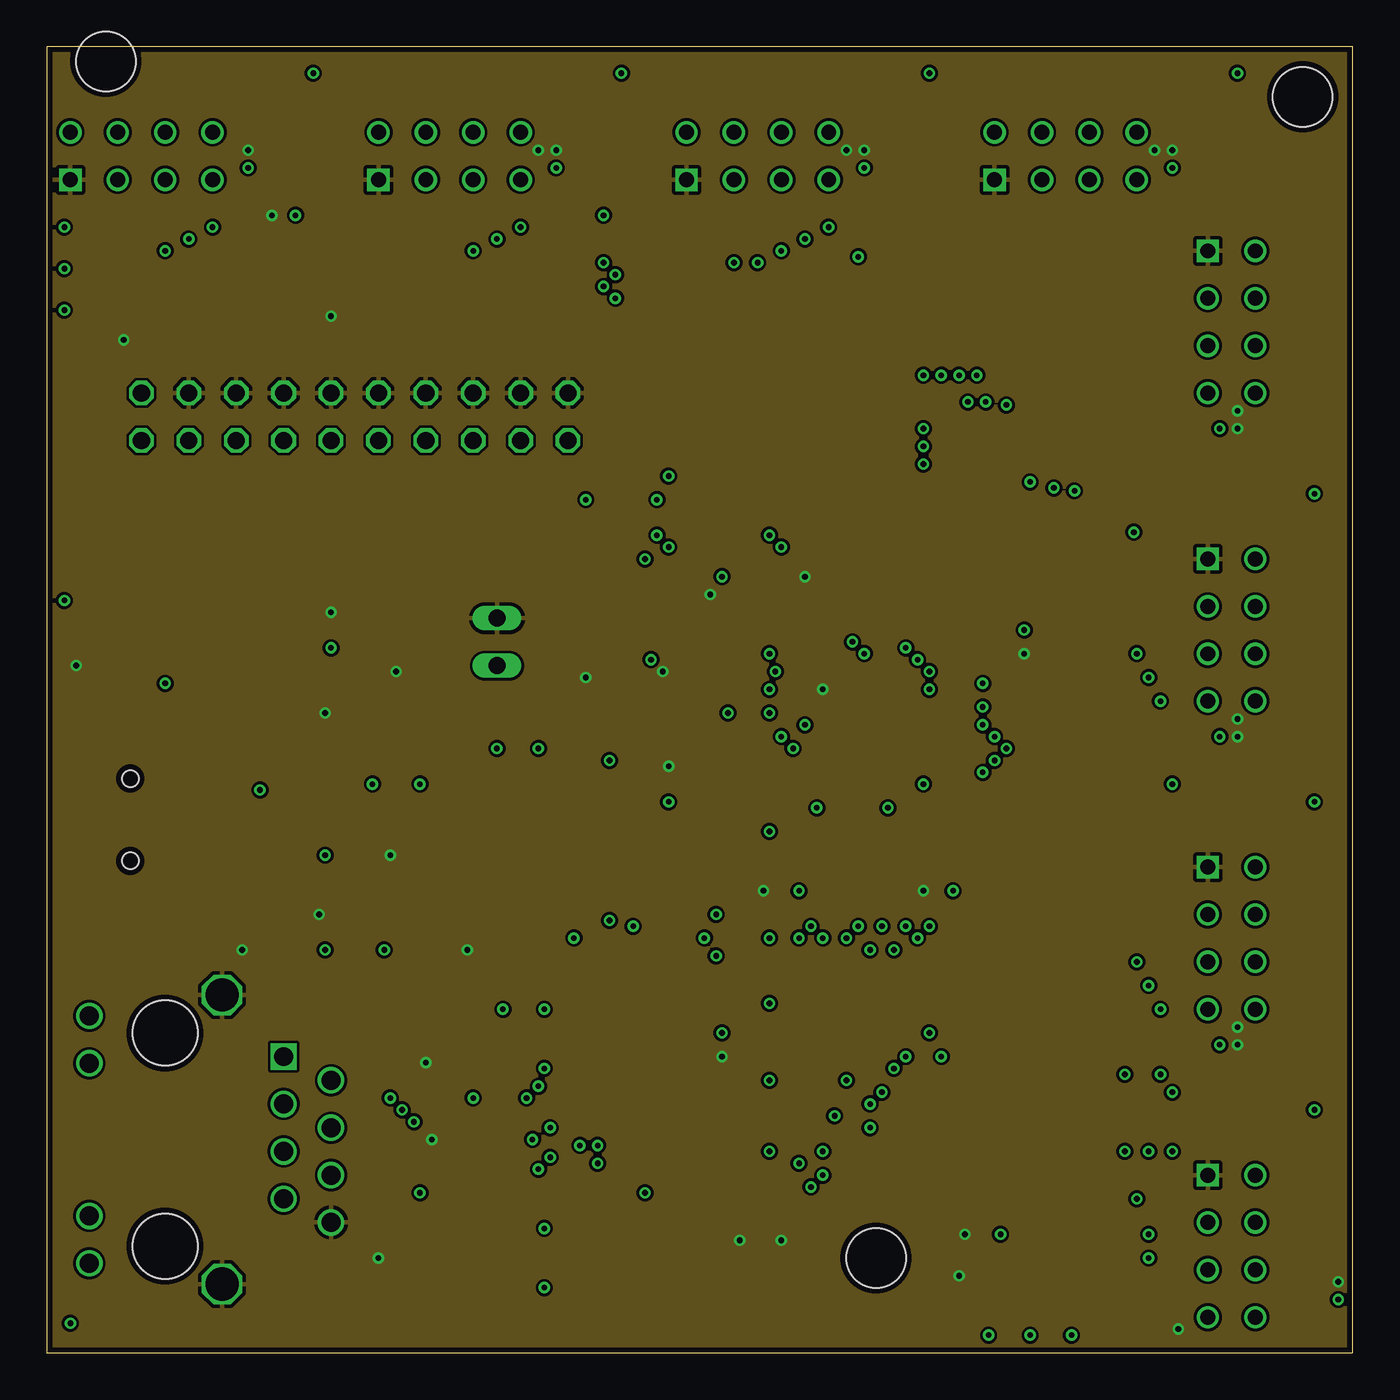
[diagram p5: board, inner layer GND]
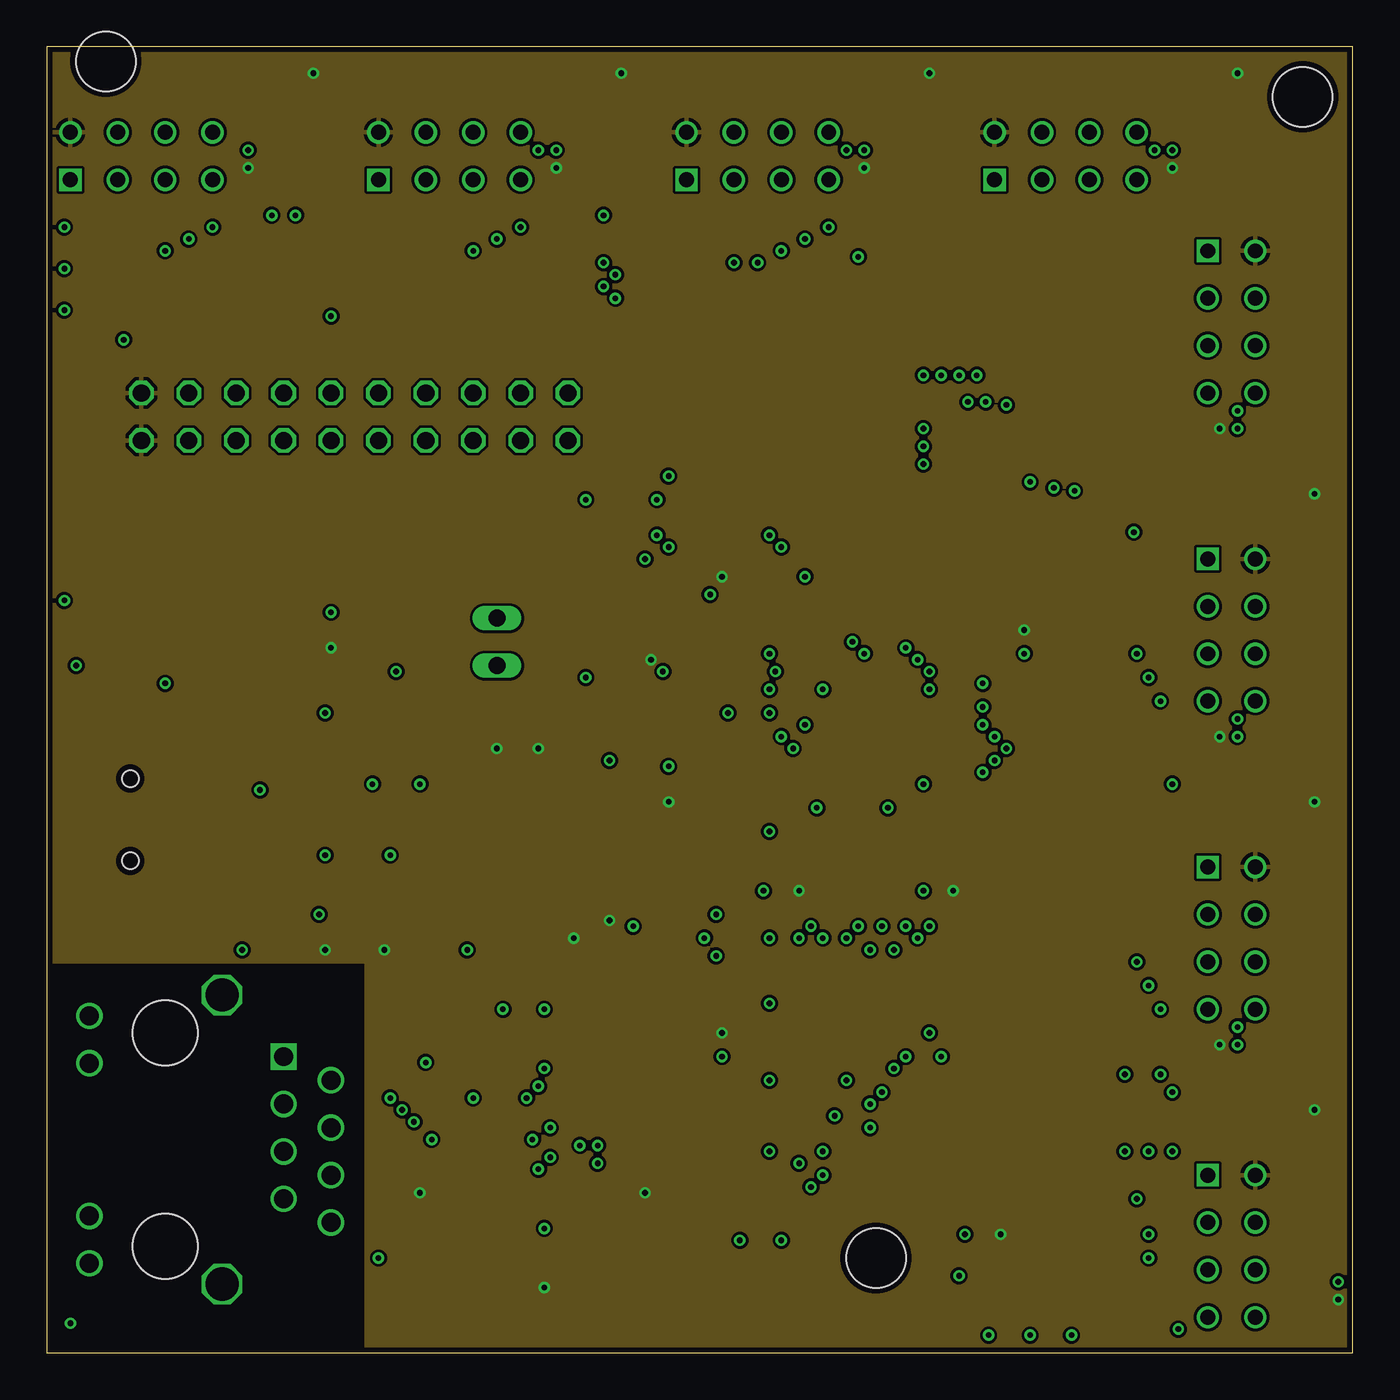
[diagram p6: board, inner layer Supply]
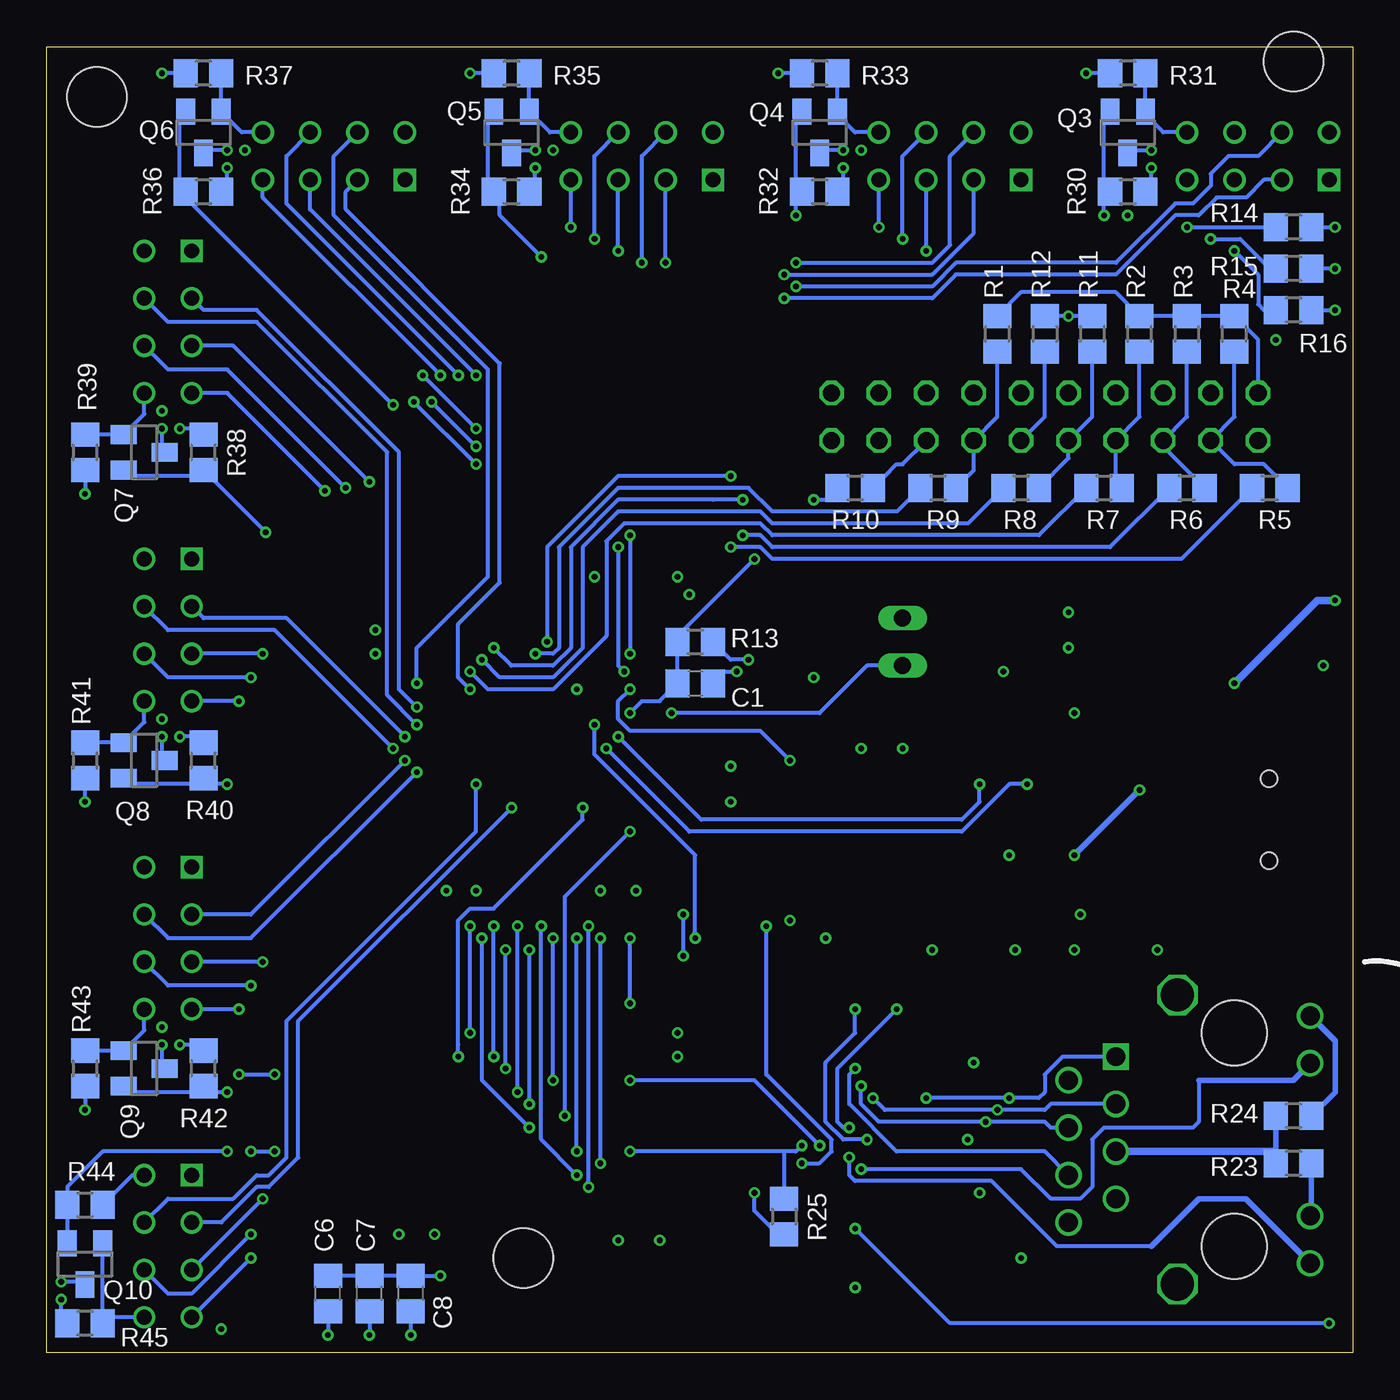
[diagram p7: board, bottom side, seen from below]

Size 70 x 70 mm. Coordinates in mm from the lower left corner, seen from the top.
Outline: 0,0 70,0 70,70 0,70 0,0
Copper layers (1+2*15+16): Top 0.035mm / dielectric 1.5mm / GND 0.035mm / dielectric 0.15mm / Supply 0.035mm / dielectric 0.2mm / Bottom 0.035mm
Design rules "PCB-POOL Standard *": minimum track width 0.15mm, minimum drill 0.3mm, track to track 0.15mm, track to pad 0.15mm, pad to pad 0.15mm, via to via 0.15mm, smd to smd 0.15mm, copper to edge 0.3mm, drill to drill 0.2mm, minimum pad ring 0.2mm, minimum via ring 0.15mm, stop-mask expansion 0.075mm, vias tented up to drill 0mil, thermal gap 0.2mm
Holes 3.2 mm at 67.31,67.31 44.45,5.08 3.17,69.22

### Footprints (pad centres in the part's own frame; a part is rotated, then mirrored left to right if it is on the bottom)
CHIP-LED0805 = smd 1.2 x 1.2: A 0,-1.05; C 0,1.05
C0805 = smd 1.3 x 1.5: 1 -0.95,0; 2 0.95,0
C/6032-28R = smd 2.55 x 2.5: + 2.525,0; - -2.525,0
RJ45-LED = drill 1.016 square: 1 -4.445,6.35 | drill 1.016 round: 2 -3.175,8.89; 3 -1.905,6.35; 4 -0.635,8.89; 5 0.635,6.35; 6 1.905,8.89; 7 3.175,6.35; 8 4.445,8.89; 11 -6.629,-4.064; 12 -4.089,-4.064; 13 4.089,-4.064; 14 6.629,-4.064 | drill 1.778 octagon: 9 -7.747,3.048; 10 7.747,3.048 | hole 3.5: -5.715,0; 5.715,0
SO-08 = smd 0.6 x 2.2: 1 -1.905,-2.6; 2 -0.635,-2.6; 3 0.635,-2.6; 4 1.905,-2.6; 5 1.905,2.6; 6 0.635,2.6; 7 -0.635,2.6; 8 -1.905,2.6
LQFP64 = smd 0.9 x 0.3: 1 -5.65,3.75; 2 -5.65,3.25; 3 -5.65,2.75; 4 -5.65,2.25; 5 -5.65,1.75; 6 -5.65,1.25; 7 -5.65,0.75; 8 -5.65,0.25; 9 -5.65,-0.25; 10 -5.65,-0.75; 11 -5.65,-1.25; 12 -5.65,-1.75; 13 -5.65,-2.25; 14 -5.65,-2.75; 15 -5.65,-3.25; 16 -5.65,-3.75; 33 5.65,-3.75; 34 5.65,-3.25; 35 5.65,-2.75; 36 5.65,-2.25; 37 5.65,-1.75; 38 5.65,-1.25; 39 5.65,-0.75; 40 5.65,-0.25; 41 5.65,0.25; 42 5.65,0.75; 43 5.65,1.25; 44 5.65,1.75; 45 5.65,2.25; 46 5.65,2.75; 47 5.65,3.25; 48 5.65,3.75 | smd 0.3 x 0.9: 17 -3.75,-5.65; 18 -3.25,-5.65; 19 -2.75,-5.65; 20 -2.25,-5.65; 21 -1.75,-5.65; 22 -1.25,-5.65; 23 -0.75,-5.65; 24 -0.25,-5.65; 25 0.25,-5.65; 26 0.75,-5.65; 27 1.25,-5.65; 28 1.75,-5.65; 29 2.25,-5.65; 30 2.75,-5.65; 31 3.25,-5.65; 32 3.75,-5.65; 49 3.75,5.65; 50 3.25,5.65; 51 2.75,5.65; 52 2.25,5.65; 53 1.75,5.65; 54 1.25,5.65; 55 0.75,5.65; 56 0.25,5.65; 57 -0.25,5.65; 58 -0.75,5.65; 59 -1.25,5.65; 60 -1.75,5.65; 61 -2.25,5.65; 62 -2.75,5.65; 63 -3.25,5.65; 64 -3.75,5.65
LQFP48 = smd 1.5 x 0.3: 1 -4.2,2.75; 2 -4.2,2.25; 3 -4.2,1.75; 4 -4.2,1.25; 5 -4.2,0.75; 6 -4.2,0.25; 7 -4.2,-0.25; 8 -4.2,-0.75; 9 -4.2,-1.25; 10 -4.2,-1.75; 11 -4.2,-2.25; 12 -4.2,-2.75; 25 4.2,-2.75; 26 4.2,-2.25; 27 4.2,-1.75; 28 4.2,-1.25; 29 4.2,-0.75; 30 4.2,-0.25; 31 4.2,0.25; 32 4.2,0.75; 33 4.2,1.25; 34 4.2,1.75; 35 4.2,2.25; 36 4.2,2.75 | smd 0.3 x 1.5: 13 -2.75,-4.2; 14 -2.25,-4.2; 15 -1.75,-4.2; 16 -1.25,-4.2; 17 -0.75,-4.2; 18 -0.25,-4.2; 19 0.25,-4.2; 20 0.75,-4.2; 21 1.25,-4.2; 22 1.75,-4.2; 23 2.25,-4.2; 24 2.75,-4.2; 37 2.75,4.2; 38 2.25,4.2; 39 1.75,4.2; 40 1.25,4.2; 41 0.75,4.2; 42 0.25,4.2; 43 -0.25,4.2; 44 -0.75,4.2; 45 -1.25,4.2; 46 -1.75,4.2; 47 -2.25,4.2; 48 -2.75,4.2
SOT23-5 = smd 1.016 x 0.508: 1 -1.27,0.953; 2 -1.27,0; 3 -1.27,-0.953; 4 1.27,-0.953; 5 1.27,0.953
SSOP28 = smd 0.4 x 1.5: 1 -4.225,-3.625; 2 -3.575,-3.625; 3 -2.925,-3.625; 4 -2.275,-3.625; 5 -1.625,-3.625; 6 -0.975,-3.625; 7 -0.325,-3.625; 8 0.325,-3.625; 9 0.975,-3.625; 10 1.625,-3.625; 11 2.275,-3.625; 12 2.925,-3.625; 13 3.575,-3.625; 14 4.225,-3.625; 15 4.225,3.625; 16 3.575,3.625; 17 2.925,3.625; 18 2.275,3.625; 19 1.625,3.625; 20 0.975,3.625; 21 0.325,3.625; 22 -0.325,3.625; 23 -0.975,3.625; 24 -1.625,3.625; 25 -2.275,3.625; 26 -2.925,3.625; 27 -3.575,3.625; 28 -4.225,3.625
ML20 = drill 0.914 octagon: 1 -11.43,-1.27; 2 -11.43,1.27; 3 -8.89,-1.27; 4 -8.89,1.27; 5 -6.35,-1.27; 6 -6.35,1.27; 7 -3.81,-1.27; 8 -3.81,1.27; 9 -1.27,-1.27; 10 -1.27,1.27; 11 1.27,-1.27; 12 1.27,1.27; 13 3.81,-1.27; 14 3.81,1.27; 15 6.35,-1.27; 16 6.35,1.27; 17 8.89,-1.27; 18 8.89,1.27; 19 11.43,-1.27; 20 11.43,1.27
IHLP1616 = smd 1.651 x 2.286: P$1 -1.905,0; P$2 1.905,0
CRYSTAL-7A = smd 1.7 x 2.4: 1 -1.85,0; 2 1.85,0
CTS406 = smd 1.9 x 1.4: 1 -2.2,-1.2; 2 2.2,-1.2; 3 2.2,1.2; 4 -2.2,1.2
SOT23 = smd 1 x 1.4: 1 -0.95,-1.1; 2 0.95,-1.1; 3 0,1.1
R0805 = smd 1.3 x 1.5: 1 -0.95,0; 2 0.95,0
JP1 = drill 0.914 long: 1 0,-1.27; 2 0,1.27
CAY16 = smd 0.5 x 0.65: 1 -1.2,-0.675; 2 -0.4,-0.675; 3 0.4,-0.675; 4 1.2,-0.675; 5 1.2,0.675; 6 0.4,0.675; 7 -0.4,0.675; 8 -1.2,0.675
USB-BMINI = smd 2.5 x 0.5: 1 0,1.6; 2 0,0.8; 3 0,0; 4 0,-0.8; 5 0,-1.6 | smd 2.5 x 2: P$6 0,4.45; P$7 0,-4.45; P$8 -5.5,4.45; P$9 -5.5,-4.45 | hole 0.9: -2.5,2.2; -2.5,-2.2
NRF24L01MOD = drill 0.8 square: 1 0,0 | drill 0.8 round: 2 0,2.54; 3 2.54,0; 4 2.54,2.54; 5 5.08,0; 6 5.08,2.54; 7 7.62,0; 8 7.62,2.54

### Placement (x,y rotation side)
100MBIT  3.49,1.59 90 top
C1  35.24,35.88 0 bottom
C2  36.51,39.37 180 top
C3  3.17,60.33 0 top
C4  3.17,58.1 0 top
C5  3.17,55.88 0 top
C6  54.93,3.17 90 bottom
C7  52.7,3.17 90 bottom
C8  50.48,3.17 90 bottom
C9  50.16,7.94 180 top
C10  38.42,41.59 0 top
C11  51.12,38.1 270 top
C12  47.62,26.04 180 top
C13  39.37,26.04 180 top
C14  34.61,30.48 90 top
C15  28.89,38.42 270 top
C16  28.89,33.97 90 top
C17  20.32,21.59 0 top
C18  12.7,21.59 180 top
C19  34.92,16.51 270 top
C20  33.34,7.62 270 top
C21  21.91,10.48 90 top
C22  39.05,4.45 0 top
C23  39.05,2.22 0 top
C24  35.56,7.62 270 top
C25  21.59,14.61 90 top
C26  19.05,5.71 270 top
C27  21.91,4.45 90 top
C28  2.22,39.37 270 top
C29  13.65,38.73 90 top
C30  4.13,35.88 180 top
C31  17.14,34.29 180 top
ETH  6.35,11.43 270 top
IC1  50.16,12.06 270 top
IC2  43.18,33.66 0 top
IC3  28.57,12.7 270 top
IC12  5.4,39.37 0 top
IC13  15.88,28.57 180 top
JTAG  16.51,50.16 0 top
L1  10.16,38.73 90 top
LED1  30.16,29.53 0 top
LED2  13.34,62.23 90 top
LED3  29.84,62.23 90 top
LED4  46.35,62.23 90 top
LED5  62.87,62.23 90 top
LED6  61.59,46.99 0 top
LED7  61.59,30.48 0 top
LED8  61.59,13.97 0 top
LED9  58.42,1.27 270 top
PWR_GOOD  18.73,38.73 180 top
Q1  31.75,36.83 270 top
Q2  33.66,3.17 180 top
Q3  12.06,65.41 180 bottom
Q4  28.57,65.41 180 bottom
Q5  45.09,65.41 180 bottom
Q6  61.59,65.41 180 bottom
Q7  64.77,48.26 270 bottom
Q8  64.77,31.75 270 bottom
Q9  64.77,15.24 270 bottom
Q10  67.94,4.76 180 bottom
R1  19.05,54.61 90 bottom
R2  11.43,54.61 90 bottom
R3  8.89,54.61 90 bottom
R4  6.35,54.61 90 bottom
R5  4.45,46.35 0 bottom
R6  8.89,46.35 0 bottom
R7  13.34,46.35 0 bottom
R8  17.78,46.35 0 bottom
R9  22.23,46.35 0 bottom
R10  26.67,46.35 0 bottom
R11  13.97,54.61 270 bottom
R12  16.51,54.61 270 bottom
R13  35.24,38.1 0 bottom
R14  3.17,60.33 180 bottom
R15  3.17,58.1 180 bottom
R16  3.17,55.88 180 bottom
R17  54.93,3.17 90 top
R18  52.7,3.17 90 top
R19  50.48,3.17 90 top
R20  35.24,35.56 270 top
R21  30.16,25.4 270 top
R22  15.88,1.59 0 top
R23  3.17,10.16 180 bottom
R24  3.17,12.7 180 bottom
R25  30.48,7.3 270 bottom
R26  24.45,21.27 90 top
R27  26.67,21.27 90 top
R28  29.21,3.17 90 top
R29  25.72,2.22 180 top
R30  12.06,62.23 0 bottom
R31  12.06,68.58 180 bottom
R32  28.57,62.23 0 bottom
R33  28.57,68.58 180 bottom
R34  45.09,62.23 0 bottom
R35  45.09,68.58 180 bottom
R36  61.59,62.23 0 bottom
R37  61.59,68.58 180 bottom
R38  61.59,48.26 90 bottom
R39  67.94,48.26 270 bottom
R40  61.59,31.75 90 bottom
R41  67.94,31.75 270 bottom
R42  61.59,15.24 90 bottom
R43  67.94,15.24 270 bottom
R44  67.94,7.94 0 bottom
R45  67.94,1.59 180 bottom
R46  13.34,64.45 180 top
R47  29.84,64.45 180 top
R48  46.35,64.45 180 top
R49  62.87,64.45 180 top
R50  63.82,46.99 90 top
R51  63.82,30.48 90 top
R52  63.82,13.97 90 top
R53  58.42,3.17 0 top
R54  16.83,38.73 270 top
R55  24.13,29.84 90 top
R56  26.35,29.84 90 top
R57  12.7,34.29 0 top
RESET  24.13,38.1 0 top
RN1  33.66,20.95 90 top
RN2  20.32,18.73 0 top
RN3  38.73,16.51 90 top
RN4  26.35,5.08 180 top
RN5  38.73,12.7 90 top
RN6  38.73,8.89 90 top
RX  26.04,26.04 180 top
TX  24.45,26.04 180 top
USB  6.99,28.57 0 top
WF1  1.27,62.87 0 top
WF2  17.78,62.87 0 top
WF3  34.29,62.87 0 top
WF4  50.8,62.87 0 top
WF5  62.23,59.05 270 top
WF6  62.23,42.55 270 top
WF7  62.23,26.04 270 top
WF8  62.23,9.53 270 top

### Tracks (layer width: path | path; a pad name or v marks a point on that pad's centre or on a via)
+3V3  (via drill 0.3)
  Top 0.203: IC3.22 23.33,10.95 C21.1 20.96,9.53 v20,8.57 | IC3.32 29.32,9.32 29.53,9.53 31.75,9.53 32.07,9.21 32.7,9.21 C20.1 | RN4.7 RN4.8 | RN4.7 RN4.6 RN4.5 | IC2.13 36.48,31.41 C14.1 v33.34,29.53 | IC2.19 40.43,27.41 40.32,27.3 C13.1 v40.32,24.77 | IC2.32 46.93,27.68 C12.1 v48.58,24.77 | C20.1 33.02,8.57 | v32.07,8.57 C20.1 | IC3.48 33.55,15.45 33.66,15.56 33.66,16.19 C19.1 35.24,17.14 v36.2,17.14 | v26.67,3.49 26.75,3.58 RN4.7 | R22.2 | C18.1 v14.92,21.59 | R55.2 v24.13,32.38 | R56.2 v26.35,32.38 | IC2.64 39.43,39.95 39.05,40.32 38.73,40.32 C10.1 | IC2.1 37.46,37.47 C2.1 C10.1 | C10.1 | C10.1 v36.2,41.59 | IC2.48 49.47,37.41 C11.1 51.43,38.73 v52.39,38.73 | RN2.5 RN2.6 RN2.7 RN2.8 19.12,21.34 | 19.12,21.34 C17.1 | 19.12,21.34 19.12,21.59 v18.1,21.59 | R27.2 R26.2 v28.25,22.22 v28.26,22.23 | 30.48,24.13 R21.2 v30.16,23.18 | v15.24,37.78 R54.2
  Top 0.406: IC12.4 8.26,38.42 9.84,36.83 L1.P$1 12.7,36.83 C29.1 v15.24,37.78 | 50.8,11.43 50.8,8.09 C9.1 v51.12,6.35 | 50.8,11.43 50.8,12.7 | 50.8,12.7 50.8,13.34 51.44,13.97 IC1.8 | 50.8,12.7 IC1.7 | IC1.3 50.8,11.43 | R22.2 16.83,2.86 13.97,5.71 13.97,10.79 | 13.97,10.79 13.97,14.61 | 13.97,14.61 13.97,21.27 C18.1 | ETH.5 13.97,10.79 | 13.97,14.61 ETH.2
  Bottom 0.203: R25.2 30.8,6.35 32.07,7.62 v32.07,8.57 | v32.38,37.15 33.34,37.15 R13.2 | R30.2 10.79,62.55 v10.79,63.5 | R31.2 v14.29,68.58 | R45.2 69.22,1.91 v69.22,2.86 | R44.2 65.41,9.53 WF8.2 | JTAG.2 5.08,54.29 R4.2 R3.2 R2.2 12.7,56.83 17.78,56.83 R1.2 | R33.2 v30.8,68.58 | R32.2 27.3,62.55 v27.3,63.5 | R34.2 43.81,62.55 v43.81,63.5 | R35.2 v47.31,68.58 | R36.2 60.33,62.55 v60.33,63.5 | R37.2 v63.82,68.58 | R38.2 61.91,49.53 v62.87,49.53 | R39.2 v67.94,46.04 | R40.2 61.91,33.02 v62.87,33.02 | v67.94,29.53 R41.2 | R43.2 v67.94,13.02 | R42.2 61.91,16.51 v62.87,16.51
  Bottom 0.305: R23.2 4.12,10.79 R24.2
  Bottom 0.406: 4.12,10.79 ETH.5
  pour Supply: -1.27,81.28 81.28,81.28 81.28,-1.27 17.14,-1.27 17.14,20.95 -1.27,20.95
+5V  (via drill 0.3)
  Top 0.203: v14.92,26.67 14.9,26.65 | USB.1 7,30.16
  Top 0.305: 14.9,26.65 IC13.20 | 7,30.16 v11.43,30.16
  Top 0.406: USB.1 6.66,30.18 4.76,32.07 4.76,35.56 C30.1 v6.35,35.88 | v0.95,40.32 C28.1 IC12.1
  Bottom 0.305: v11.43,30.16 v14.92,26.67
  Bottom 0.406: v6.35,35.88 1.91,40.32 v0.95,40.32
EEPROM_CS  (via drill 0.3)
  Top 0.203: IC2.20 40.93,28.86 v41.27,29.21 | IC1.1 47.56,15.5 v47.94,15.88
  Bottom 0.203: v41.27,29.21 41.27,28.57 46.04,23.81 47.31,23.81 47.94,23.18 47.94,16.51 v47.94,15.88
GND  (via drill 0.3)
  Top 0.203: v36.2,15.88 35.24,15.88 C19.2 34.31,14.95 IC3.47 | 22.23,15.55 23.33,14.45 IC3.15 | 22.23,15.55 C25.2 | 22.23,15.55 22.23,15.56 v20.32,15.56 | IC3.19 22.93,12.45 C21.2 v20.64,11.43 | IC2.12 35.08,31.91 C14.2 v33.34,31.43 | IC2.18 39.93,27.23 39.61,27.23 C13.2 v38.42,24.77 | IC2.31 46.43,26.28 C12.2 46.99,25.72 v46.99,24.77 | R29.1 25.4,0.95 22.88,0.95 C27.- 19.06,4.76 C26.2 18.73,5.08 v17.78,5.08 | IC3.35 IC3.36 31.32,7.73 31.75,7.3 32.7,7.3 C20.2 C24.2 36.2,6.03 v39.37,6.03 40,5.4 C22.2 C23.2 | C18.2 v10.48,21.59 | IC13.7 C31.2 v14.92,34.29 | IC13.25 18.15,26.41 v18.41,26.67 18.8,26.29 IC13.26 | IC13.18 13.6,23.86 13.97,23.5 v14.61,23.5 15.24,23.5 15.55,23.8 IC13.21 | IC2.63 39.93,41.03 C10.2 v40.64,41.59 | C2.2 v35.56,40.64 | C15.2 v28.89,36.2 C16.2 | IC2.47 50.87,36.91 C11.2 51.43,37.47 v52.39,37.47 | LED9.C v60.64,1.27 | IC2.60 41.43,35.72 v41.59,35.56 | v12.06,60.96 12.06,62.01 LED2.C | C3.2 C4.2 v4.13,54.29 v4.12,54.3 C5.2 | LED3.C 27.62,62.23 26.35,63.5 v26.35,64.45 | LED4.C 44.13,62.23 42.86,63.5 v42.86,64.45 | LED5.C 60.64,62.23 59.37,63.5 v59.37,64.45 | LED6.C 61.59,49.21 62.87,50.48 v63.82,50.48 | LED7.C 61.59,32.7 62.87,33.97 v63.82,33.97 | LED8.C 61.59,16.19 62.87,17.46 v63.82,17.46 | C17.2 v22.54,21.59 | PWR_GOOD.C v18.73,36.51
  Top 0.406: USB.5 5.41,26.98 3.49,28.89 3.49,35.56 C30.2 2.22,36.83 | 2.22,36.83 C28.2 2.54,38.42 3.49,39.37 IC12.2 | v1.59,36.83 2.22,36.83 | C29.2 v15.24,39.69 | IC1.4 48.9,10.16 49.53,9.53 49.53,8.09 C9.2 v49.21,6.35
  Bottom 0.203: C1.2 34.29,36.51 v33.02,36.51 | Q3.3 11.92,64.45 v10.79,64.45 | Q10.3 68.09,3.81 v69.22,3.81 | R11.1 v15.24,55.56 R12.1 | C6.2 C7.2 C8.2 v48.9,4.13 | Q4.3 28.43,64.45 v27.3,64.45 | v43.81,64.45 44.94,64.45 Q5.3 | Q6.3 61.45,64.45 v60.33,64.45 | Q7.3 63.82,48.41 v63.82,49.53 | Q8.3 63.82,31.9 v63.82,33.02 | Q9.3 63.82,15.39 v63.82,16.51
  other vias: 37.15,6.03
  pour GND: -0.64,80.64 80.64,80.64 80.64,-0.64 -0.64,-0.64
JTAG-SRST
  Bottom 0.203: JTAG.15 24.13,47.62 24.45,47.62 25.08,46.99 25.09,46.99 R10.2
JTAG-TCK
  Bottom 0.203: R11.2 13.97,50.16 JTAG.9 15.24,47.94 R8.2
JTAG-TDI
  Bottom 0.203: R3.1 8.89,50.16 JTAG.5 10.16,48.58 R6.2
JTAG-TDO
  Bottom 0.203: R1.1 19.05,50.16 JTAG.13 20.32,47.31 R9.2
JTAG-TMS
  Bottom 0.203: R2.1 11.43,50.16 JTAG.7 12.7,46.67 R7.2
JTAG-TRST
  Bottom 0.203: R4.1 6.35,50.16 JTAG.3 6.35,47.62 4.76,47.62 R5.2
LED  (via drill 0.3)
  Top 0.203: IC2.4 38.39,35.91 v38.73,35.56 | LED1.C v30.16,31.75
  Bottom 0.203: v38.73,35.56 39.37,34.92 39.37,33.97 38.73,33.34 31.75,33.34 v30.16,31.75
MII_COL  (via drill 0.3)
  Top 0.203: RN5.2 39.6,12.3 40.01,12.7 v42.23,12.7 | IC2.17 39.43,27.94 v38.73,27.94
  Bottom 0.203: v38.73,27.94 42.23,24.45 v42.23,12.7
MII_CRS  (via drill 0.3)
  Top 0.203: IC2.14 36.62,30.91 35.88,30.16 35.88,25.08 38.1,22.86 39.69,22.86 v40.32,22.23 | RN6.4 39.94,10.09 40.01,10.16 v40.32,10.16
  Bottom 0.203: v40.32,10.16 v40.32,22.23
MII_INT
  Top 0.203: IC3.7 28.32,18.8 32.38,22.86 35.56,22.86 37.15,21.27 41.59,21.27 42.23,21.91 42.23,23.18 41.43,23.98 IC2.21
MII_MDC  (via drill 0.3)
  Top 0.203: IC3.31 28.82,9.46 v29.53,10.16 | IC2.9 33.09,33.41 31.43,31.75 v31.43,22.86
  Bottom 0.203: v29.53,10.16 28.57,10.16 27.94,10.79 27.94,11.43 31.43,14.92 v31.43,22.86
MII_MDIO  (via drill 0.3)
  Top 0.203: IC3.30 28.32,9.91 v29.53,11.11 | IC2.16 37.15,29.91 37.15,25.08 38.1,24.13 40.64,24.13 41.59,23.18 v41.59,22.23 | v38.73,10.79 v41.59,10.79
  Bottom 0.203: v29.53,11.11 29.84,10.79 30.48,10.79 | 30.48,10.79 v38.73,10.79 | v41.59,10.79 v41.59,22.23 | 30.48,10.79 R25.1
MII_RX_CLK  (via drill 0.3)
  Top 0.203: IC2.15 36.76,30.41 36.51,30.16 36.51,25.08 38.1,23.5 40.32,23.5 v40.96,22.86 | RN6.2 39.92,8.49 40.32,8.89 v40.96,8.89
  Bottom 0.203: v40.96,8.89 v40.96,22.86
MII_RX_DV  (via drill 0.3)
  Top 0.203: RN6.3 39.77,9.29 40.01,9.53 v41.59,9.53 | IC2.23 42.43,24.25 43.5,23.18 v43.5,22.86
  Bottom 0.203: v41.59,9.53 43.5,11.43 v43.5,22.86
MII_RX_ER  (via drill 0.3)
  Top 0.203: IC2.29 45.43,27.33 45.09,26.99 45.09,24.77 46.67,23.18 v46.67,22.23 | RN5.1 39.76,11.5 40.32,12.06 v44.13,12.06
  Bottom 0.203: v44.13,12.06 46.67,14.61 v46.67,22.23
MII_RXD0  (via drill 0.3)
  Top 0.203: RN5.3 39.77,13.1 40.01,13.34 v44.13,13.34 | IC2.24 42.93,24.38 44.13,23.18 v44.13,21.59
  Bottom 0.203: v44.13,13.34 v44.13,21.59
MII_RXD1  (via drill 0.3)
  Top 0.203: IC2.25 43.43,24.52 44.77,23.18 v44.77,22.86 | RN5.4 39.94,13.9 40.01,13.97 v44.77,13.97
  Bottom 0.203: v44.77,13.97 v44.77,22.86
MII_RXD2  (via drill 0.3)
  Top 0.203: IC2.26 43.93,24.65 45.4,23.18 v45.4,21.59 | RN3.1 39.48,15.24 v45.4,15.24
  Bottom 0.203: v45.4,15.24 v45.4,21.59
MII_RXD3  (via drill 0.3)
  Top 0.203: IC2.27 44.43,24.79 46.04,23.18 v46.04,22.86 | RN3.2 40.09,16.11 40.32,15.88 v46.04,15.88
  Bottom 0.203: v46.04,15.88 v46.04,22.86
MII_TX_CLK  (via drill 0.3)
  Top 0.203: IC2.11 37.51,32.38 33.34,32.38 32.7,31.75 32.7,27.62 38.1,22.23 v38.73,22.23 | RN3.3 38.97,16.91 38.73,17.14 v38.73,18.73
  Bottom 0.203: v38.73,18.73 v38.73,22.23
MII_TX_EN  (via drill 0.3)
  Top 0.203: IC2.30 45.93,27.2 45.72,26.99 45.72,24.77 47.31,23.18 v47.31,22.86 | RN3.4 40.08,17.71 40.64,17.14 v47.31,17.14
  Bottom 0.203: v47.31,17.14 v47.31,22.86
MII_TXD0
  Top 0.203: IC2.33 49.47,29.91 50.48,28.89 50.48,24.45 45.72,19.68 34.4,19.68 RN1.1
MII_TXD1
  Top 0.203: RN1.2 34.41,20.64 46.04,20.64 49.85,24.45 49.85,28.26 48.9,29.21 48.26,29.21 47.94,29.53 47.94,30.16 48.19,30.41 IC2.34
MII_TXD2  (via drill 0.3)
  Top 0.203: IC2.10 33.22,32.91 32.07,31.75 32.07,27.62 35.88,23.81 v35.88,23.5 | RN1.3 34.41,21.27 v35.88,21.27
  Bottom 0.203: v35.88,21.27 v35.88,23.5
MII_TXD3  (via drill 0.3)
  Top 0.203: IC2.61 40.93,38.39 40.64,38.1 v40.64,33.66 | v35.24,22.23 35.17,22.16 RN1.4
  Bottom 0.203: v40.64,33.66 40.64,32.07 35.24,26.67 v35.24,22.23
N$1
  Top 0.203: IC3.3 30.32,18.26 31.82,19.75 RN1.8
N$2
  Top 0.203: IC3.4 29.82,18.39 31.98,20.55 RN1.7
N$3
  Top 0.203: IC3.5 29.32,18.53 32.15,21.36 RN1.6
N$4
  Top 0.203: IC3.6 28.82,18.66 32.31,22.16 RN1.5
N$5
  Top 0.203: IC3.1 31.32,17.99 31.75,18.41 36.2,18.41 37.7,16.91 RN3.6
N$6
  Top 0.203: IC3.2 30.82,18.12 31.75,19.05 36.2,19.05 37.53,17.71 RN3.5
N$7
  Top 0.203: IC3.45 36.17,13.95 37.53,15.31 RN3.8
N$8
  Top 0.203: IC3.46 36.04,14.45 37.7,16.11 RN3.7
N$9
  Top 0.203: IC3.43 36.45,12.95 36.59,13.1 RN5.6
N$10
  Top 0.203: IC3.44 36.31,13.45 36.76,13.9 RN5.5
N$11
  Top 0.203: IC3.42 36.76,12.45 36.91,12.3 RN5.7
N$12
  Top 0.203: IC3.41 36.63,11.95 37.08,11.5 RN5.8
N$13
  Top 0.203: IC3.39 36.04,10.95 37.7,9.29 RN6.6
N$14
  Top 0.203: IC3.38 35.91,10.45 37.87,8.49 RN6.7
N$15
  Top 0.203: IC3.40 36.17,11.45 37.53,10.09 RN6.5
N$16  (via drill 0.3)
  Top 0.203: IC3.20 25.6,11.95 25.72,12.06 v26.99,12.06 | v24.45,18.41 R26.1
  Bottom 0.203: v26.99,12.06 27.3,12.06 27.62,12.38 27.62,15.24 v24.45,18.41
N$17  (via drill 0.3)
  Top 0.203: v0.95,60.33 R14.1
  Bottom 0.203: R14.1 v0.95,60.33
N$18
  Top 0.203: R28.1 31.2,2.23 Q2.3 31.68,1.98 33.02,0.64 36.83,0.64 38.1,1.91 C23.1
N$19  (via drill 0.3)
  Top 0.203: C4.1 v0.95,58.1
  Bottom 0.203: v0.95,58.1 C4.1
N$20
  Top 0.203: IC3.24 24.45,9.95 24.45,2.54 R29.2
N$21
  Top 0.203: 27.94,12.06 27.05,12.95 IC3.18 22.3,12.95 C25.1 | 27.94,12.06 29.84,12.06 31.96,9.95 IC3.37 34.18,9.95 C24.1 | 27.94,12.06 27.3,11.43 26.99,11.43 26.01,10.45 IC3.23 23.47,10.45 23.18,10.16 23.18,8.26 21.91,6.99 C27.+ 19.36,6.97 C26.1
N$22  (via drill 0.3)
  Top 0.203: IC3.21 26.02,11.45 v26.04,11.43 | v26.67,18.41 R27.1
  Bottom 0.203: v26.04,11.43 27.3,11.43 28.26,12.38 28.26,15.56 26.67,17.14 v26.67,18.41
N$23  (via drill 0.3)
  Top 0.203: RN4.3 25.95,7.22 26.32,7.59 IC3.26 26.35,8.53 v26.35,9.84
  Bottom 0.203: v26.35,9.84 17.78,9.84 16.19,8.26 14.61,8.26 13.97,8.89 13.97,11.43 13.34,12.06 8.57,12.06 8.26,12.38 8.26,14.61
  Bottom 0.305: ETH.12 3.2,14.61 8.26,14.61
N$24  (via drill 0.3)
  Top 0.203: 26.82,5.83 RN4.2 26.67,5.84 v26.67,6.67 26.82,6.82 IC3.27 | 100MBIT.C v1.27,1.59
  Bottom 0.203: v1.27,1.59 21.59,1.59 v26.67,6.67
N$25  (via drill 0.3)
  Top 0.203: RN4.1 27.62,5.83 27.62,7.3 27.32,7.6 IC3.28 27.3,8.52 27.3,10.16 v26.99,10.48
  Bottom 0.203: 10.79,5.71 15.88,5.71 19.37,9.21 26.67,9.21 26.99,9.53 v26.99,10.48
  Bottom 0.305: ETH.14 5.74,8.26 8.26,8.26 10.79,5.71
N$26  (via drill 0.3)
  Top 0.203: v26.67,15.24 26.46,15.45 IC3.13 23.81,15.45 23.81,15.56 21.52,17.85 RN2.4
  Bottom 0.203: v26.67,15.24 26.99,14.92 26.99,13.34 24.45,10.79 16.51,10.79 ETH.6
N$27  (via drill 0.3)
  Top 0.203: RN2.3 20.72,17.23 19.68,16.19 v19.68,12.38 | IC3.14 25.69,14.95 v26.35,14.29
  Bottom 0.203: ETH.4 16.19,12.06 16.51,12.38 v19.68,12.38 25.4,12.38 26.35,13.34 v26.35,14.29
N$28  (via drill 0.3)
  Top 0.203: IC3.16 25.42,13.95 v25.72,13.65 | RN2.2 19.92,17.38 19.05,16.51 v19.05,13.02
  Bottom 0.203: v25.72,13.65 25.08,13.02 v19.05,13.02 16.51,13.02 16.19,13.34 ETH.3
N$29  (via drill 0.3)
  Top 0.203: IC3.17 23.06,13.45 v22.86,13.65 | RN2.1 19.12,17.53 18.41,16.83 v18.41,13.65
  Bottom 0.203: ETH.1 15.56,15.88 16.51,14.92 16.51,13.97 16.83,13.65 v18.41,13.65 v22.86,13.65
N$30
  Bottom 0.203: WF1.8 10.16,65.41 11.12,66.36 Q3.1 R31.1
N$31
  Bottom 0.305: ETH.11 0.95,16.73 0.95,13.97 R24.1
N$32
  Bottom 0.305: ETH.13 2.23,7.4 R23.1
N$33
  Top 0.203: 100MBIT.A R22.1
N$34
  Bottom 0.203: WF2.8 26.67,65.41 27.62,66.36 Q4.1 R33.1
N$35
  Bottom 0.203: WF3.8 43.03,65.41 Q5.1 R35.1
N$36
  Bottom 0.203: WF4.8 59.55,65.41 Q6.1 R37.1
N$37
  Bottom 0.203: WF5.8 64.77,50.31 Q7.1 R39.1
N$38
  Bottom 0.203: WF6.8 64.77,33.8 Q8.1 R41.1
N$39
  Bottom 0.203: WF7.8 64.77,17.29 Q9.1 R43.1
N$40
  Bottom 0.203: WF8.8 66.68,1.91 R45.1 Q10.1
N$41
  Top 0.406: USB.2 10.95,29.38 12.3,28.02 IC13.16
N$42
  Top 0.406: USB.3 10.48,28.57 11.65,27.4 IC13.15
N$43
  Top 0.203: IC13.23 16.85,27.01 17.14,27.3 20.32,27.3 22.23,25.4 24.03,25.4 TX.C
N$44
  Top 0.203: IC13.22 16.2,27 17.14,27.94 20.32,27.94 22.23,26.04 25.08,26.04 26.04,25.08 RX.C
N$45
  Top 0.406: IC12.5 9.84,40.32 L1.P$2
N$46
  Top 0.203: TX.A 24.13,27.4 R55.1
N$47
  Top 0.203: RX.A 26.35,27.4 R56.1
N$48
  Top 0.203: R54.1 17.15,40.01 18.41,40.01 18.64,39.78 PWR_GOOD.A
N$49
  Top 0.203: LED2.A 14.61,62.45 14.61,64.14 R46.1
N$50
  Top 0.203: LED3.A 31.11,62.45 31.11,64.13 R47.1
N$51
  Top 0.203: LED4.A 47.62,62.45 47.62,64.14 R48.1
N$52
  Top 0.203: LED5.A 64.14,62.45 64.14,64.13 R49.1
N$53
  Top 0.203: LED6.A 61.81,45.72 63.5,45.72 R50.1
N$54
  Top 0.203: LED7.A 61.81,29.21 63.5,29.21 R51.1
N$55
  Top 0.203: LED8.A 61.59,12.7 63.5,12.7 R52.1
N$56
  Top 0.203: LED9.A 57.47,1.37 R53.1
N$57
  Top 0.203: R21.1 LED1.A
N$58  (via drill 0.3)
  Top 0.203: v0.95,55.88 R16.1
  Bottom 0.203: R16.1 v0.95,55.88
N$59  (via drill 0.3)
  Top 0.203: v54.93,0.95 C6.1
  Bottom 0.203: C6.1 v54.93,0.95
N$60  (via drill 0.3)
  Top 0.203: v52.7,0.95 C7.1
  Bottom 0.203: C7.1 v52.7,0.95
N$61  (via drill 0.3)
  Top 0.203: v50.48,0.95 C8.1
  Bottom 0.203: C8.1 v50.48,0.95
N$165
  Top 0.203: R20.2 35.54,34.91 IC2.6
N$168
  Top 0.203: 36.2,37.78 36.51,37.47 36.51,35.88 36.98,35.41 IC2.5
  Top 0.254: 36.2,37.78 35.88,38.1 32.38,38.1 31.8,38.68 Q1.1 31.06,39.37 C15.1
N$169
  Top 0.203: C16.1 29.21,33.02 29.53,33.34
  Top 0.254: R20.1 34.92,36.51 33.66,35.24 32.01,35.24 Q1.2 31.49,34.98 30.16,33.66 29.53,33.02 C16.1
N$173
  Bottom 0.203: R12.2 16.51,50.16 JTAG.11
PHY_RESET  (via drill 0.3)
  Top 0.203: IC3.29 27.82,10.36 v28.57,11.11 | IC2.22 41.93,24.11 42.86,23.18 v42.86,22.23 | v38.73,14.61 v42.86,14.61
  Bottom 0.203: v28.57,11.11 32.07,14.61 v38.73,14.61 | v42.86,14.61 v42.86,22.23
RESET_CFG  (via drill 0.3)
  Top 0.203: IC2.8 36.9,33.91 v36.51,34.29
  Bottom 0.203: v36.51,34.29 28.57,34.29 26.04,36.83 RESET.1
SLEEP
  Top 0.203: IC13.12 12.95,33.09 R57.1 8.89,34.29 4.76,38.42 IC12.3
SPI3_MISO  (via drill 0.3)
  Top 0.203: WF1.7 v8.89,60.33 v25.4,60.33 v41.91,60.33 41.91,59.37 v48.9,52.39 v50.32,50.96 v55.09,46.2 59.69,41.59 v59.69,34.92 v59.69,18.41 v59.69,14.92 59.69,5.71 v59.05,5.08 54.93,5.08 R17.2 | IC2.52 45.43,46.06 v46.99,47.62 | IC1.2 49.21,12.7 49.21,14.92 v57.78,14.92
  Bottom 0.203: v25.4,60.33 WF2.7 | v41.91,60.33 WF3.7 | v59.69,34.92 WF6.7 | v59.69,18.41 WF7.7 | v59.05,5.08 WF8.7 | v8.89,60.33 R14.2 | v59.69,14.92 v57.78,14.92 | v46.99,47.62 | v50.32,50.96 v46.99,47.62 | WF5.7 60.33,51.44 v55.09,46.2 | WF4.7 58.42,61.91 v48.9,52.39
SPI3_MOSI  (via drill 0.3)
  Top 0.203: WF1.6 7.62,64.14 v7.62,59.69 v24.13,59.69 v40.64,59.69 v47.94,52.39 v49.37,50.96 v53.98,46.35 59.05,41.27 v59.05,36.2 v59.05,19.68 v59.05,10.79 v59.05,6.35 53.98,6.35 52.7,5.08 R18.2 | IC2.53 44.93,46.52 v46.99,48.58 | IC1.5 54.29,10.16 54.93,10.79 v57.78,10.79
  Bottom 0.203: WF2.6 24.13,64.14 v24.13,59.69 | WF3.6 40.64,64.14 v40.64,59.69 | WF4.6 57.15,64.14 57.15,61.59 v47.94,52.39 | WF5.6 63.5,52.7 60.33,52.7 v53.98,46.35 | WF6.6 63.5,36.2 v59.05,36.2 | WF7.6 63.5,19.68 v59.05,19.68 | v59.05,6.35 62.23,3.17 63.5,3.17 WF8.6 | v7.62,59.69 6.03,59.69 4.45,58.1 R15.2 | v59.05,10.79 v57.78,10.79 | v46.99,48.58 | v49.37,50.96 v46.99,48.58
SPI3_SCK  (via drill 0.3)
  Top 0.203: 58.42,11.43 v58.42,8.26 54.93,8.26 52.07,5.4 50.8,5.4 50.48,5.08 R19.2 | 58.42,11.43 v58.42,20.95 v58.42,37.47 58.42,40.96 v52.7,46.67 | IC2.51 45.93,45.61 49.85,49.53 | WF1.5 v6.35,59.05 v22.86,59.05 v39.37,59.05 40.32,59.05 v46.99,52.39 49.85,49.53 | 58.42,11.43 IC1.6 | v52.7,46.67 49.85,49.53 | v52.7,46.67 52.86,46.51
  Bottom 0.203: v22.86,59.05 WF2.5 | v39.37,59.05 WF3.5 | WF5.5 60.01,53.98 v52.7,46.67 | v58.42,37.47 WF6.5 | v58.42,20.95 WF7.5 | v58.42,8.26 WF8.5 | v6.35,59.05 5.08,57.78 5.08,56.2 4.76,55.88 R16.2 | WF4.5 55.88,61.28 v46.99,52.39
SRST  (via drill 0.3)
  Top 0.203: IC2.7 38.62,34.41 v38.73,34.29 | v32.07,42.55 v28.89,45.72
  Bottom 0.203: v38.73,34.29 38.1,34.92 37.15,34.92 C1.1 R13.1 36.19,38.42 v32.07,42.55 | R10.1 28.25,45.72 v28.89,45.72
TCK  (via drill 0.3)
  Top 0.203: IC2.49 46.93,37.41 v46.67,37.15
  Bottom 0.203: R8.1 20.64,44.45 31.11,44.45 31.75,45.09 39.37,45.09 41.27,43.18 41.27,37.78 42.86,36.2 45.72,36.2 v46.67,37.15
TDI  (via drill 0.3)
  Top 0.203: IC2.50 46.43,38.17 v46.04,37.78 | v32.7,43.81 v32.7,45.72
  Bottom 0.203: R6.1 13.02,43.18 31.11,43.18 31.75,43.81 v32.7,43.81 | v46.04,37.78 45.09,36.83 42.86,36.83 41.91,37.78 41.91,43.18 39.37,45.72 34.29,45.72 v32.7,45.72
TDO  (via drill 0.3)
  Top 0.203: IC2.55 43.93,37.58 v43.81,37.47
  Bottom 0.203: R9.1 24.45,45.09 31.11,45.09 32.38,46.35 39.37,46.35 42.55,43.18 42.55,37.78 42.86,37.47 v43.81,37.47
TMS  (via drill 0.3)
  Top 0.203: IC2.46 47.52,36.41 v47.31,36.51
  Bottom 0.203: R7.1 16.82,43.81 31.11,43.81 31.75,44.45 39.05,44.45 40.01,43.5 40.01,38.42 42.86,35.56 46.35,35.56 v47.31,36.51
TRST  (via drill 0.3)
  Top 0.203: IC2.56 43.43,38.35 v43.18,38.1 | v33.34,43.18 v33.34,46.99
  Bottom 0.203: R5.1 9.21,42.55 31.11,42.55 31.75,43.18 v33.34,43.18 | v43.18,38.1 43.18,43.18 39.37,46.99 34.29,46.99 v33.34,46.99
USART1_RX  (via drill 0.3)
  Top 0.203: IC2.43 47.6,34.91 45.72,33.02 v39.37,33.02 | v20,30.48 20.1,30.58 IC13.1
  Bottom 0.203: v39.37,33.02 34.92,28.57 20.95,28.57 20,29.53 v20,30.48
USART1_TX  (via drill 0.3)
  Top 0.203: IC2.42 47.74,34.41 45.72,32.38 v40.01,32.38 | v17.46,30.48 17.5,30.52 IC13.5
  Bottom 0.203: v40.01,32.38 35.56,27.94 20.95,27.94 18.41,30.48 v17.46,30.48
VCCIO
  Top 0.203: IC13.17 12.95,26.29 15.24,28.57 16.51,28.57 18.15,30.21 IC13.4 18.15,34.23 C31.1 16.83,35.56 14.92,35.56 13.97,34.61 R57.2
WF_CE1  (via drill 0.3)
  Top 0.203: IC2.2 38.17,36.91 v38.73,37.47 | v30.48,56.52 31.75,56.52 38.73,49.53 v38.73,43.81
  Bottom 0.203: v38.73,43.81 v38.73,37.47 | WF1.3 4.76,62.87 5.71,61.91 7.3,61.91 8.26,60.96 9.53,60.96 12.7,57.78 21.27,57.78 22.54,56.52 v30.48,56.52
WF_CE2  (via drill 0.3)
  Top 0.203: IC2.62 40.43,40.11 41.27,40.96 41.27,43.81 40.01,45.09 40.01,50.16 32.38,57.78 v30.48,57.78
  Bottom 0.203: WF2.3 20.32,60.01 22.54,57.78 v30.48,57.78
WF_CE3  (via drill 0.3)
  Top 0.203: IC2.58 42.43,43.93 41.27,45.09 41.27,50.8 36.83,55.24 v36.83,58.42
  Bottom 0.203: v36.83,58.42 WF3.3
WF_CE4  (via drill 0.3)
  Top 0.203: IC2.45 47.65,35.91 v47.31,35.56
  Bottom 0.203: WF4.3 53.98,62.23 53.98,61.28 45.72,53.02 45.72,41.27 47.94,39.05 47.94,36.2 v47.31,35.56
WF_CE5  (via drill 0.3)
  Top 0.203: IC2.41 49.46,33.91 v50.16,34.61
  Bottom 0.203: WF5.3 61.59,55.88 58.74,55.88 51.12,48.26 51.12,35.56 v50.16,34.61
WF_CE6  (via drill 0.3)
  Top 0.203: IC2.39 50.69,32.91 v50.8,33.02
  Bottom 0.203: WF6.3 61.59,39.37 57.15,39.37 v50.8,33.02
WF_CE7  (via drill 0.3)
  Top 0.203: IC2.37 50.65,31.91 v50.8,31.75
  Bottom 0.203: v50.8,31.75 59.05,23.5 WF7.3
WF_CE8  (via drill 0.3)
  Top 0.203: IC2.28 44.93,29.05 v45.09,29.21
  Bottom 0.203: WF8.3 60.64,6.99 58.74,8.89 58.1,8.89 56.52,10.48 56.52,17.78 v45.09,29.21
WF_CS1  (via drill 0.3)
  Top 0.203: R46.2 10.16,66.67 5.08,66.67 WF1.4 | IC2.3 38.95,36.41 v39.05,36.51 | v29.84,57.15 32.07,57.15 39.37,49.85 v39.37,43.18
  Bottom 0.203: v29.84,57.15 22.54,57.15 21.27,58.42 12.7,58.42 9.53,61.59 8.57,61.59 7.62,62.55 7.62,63.18 6.67,64.14 5.08,64.14 WF1.4 | v39.05,36.51 39.37,36.83 v39.37,43.18
WF_CS2  (via drill 0.3)
  Top 0.203: IC2.59 41.93,43.8 40.64,45.09 40.64,50.48 32.7,58.42 v29.84,58.42 | R47.2 26.67,66.67 21.59,66.67 WF2.4
  Bottom 0.203: WF2.4 21.59,64.14 21.59,59.37 22.54,58.42 v29.84,58.42
WF_CS3  (via drill 0.3)
  Top 0.203: IC2.57 42.93,44.06 41.91,45.09 41.91,51.12 38.1,54.93 v38.1,58.42 | R48.2 43.18,66.67 38.1,66.67 WF3.4
  Bottom 0.203: WF3.4 38.1,64.14 v38.1,58.42
WF_CS4  (via drill 0.3)
  Top 0.203: IC2.44 49.69,35.41 v50.16,35.88 | R49.2 59.69,66.67 54.61,66.67 WF4.4
  Bottom 0.203: WF4.4 54.61,64.14 54.61,60.96 46.35,52.7 46.35,41.59 50.16,37.78 v50.16,35.88
WF_CS5  (via drill 0.3)
  Top 0.203: IC2.40 49.91,33.41 v50.16,33.66 | R50.2 66.04,50.16 66.04,55.24 WF5.4
  Bottom 0.203: WF5.4 63.5,55.24 58.74,55.24 51.75,48.26 51.75,35.24 v50.16,33.66
WF_CS6  (via drill 0.3)
  Top 0.203: IC2.38 51.41,32.41 v51.44,32.38 | R51.2 66.04,33.65 66.04,38.73 WF6.4
  Bottom 0.203: WF6.4 63.5,38.73 57.78,38.73 v51.44,32.38
WF_CS7  (via drill 0.3)
  Top 0.203: IC2.36 49.88,31.41 v50.16,31.11 | R52.2 66.04,17.14 66.04,22.23 WF7.4
  Bottom 0.203: WF7.4 63.5,22.23 59.05,22.23 v50.16,31.11
WF_CS8  (via drill 0.3)
  Top 0.203: R53.2 61.91,5.71 63.5,5.71 WF8.4 | IC2.35 47.41,30.91 v46.99,30.48
  Bottom 0.203: WF8.4 63.5,8.26 60.01,8.26 58.74,9.53 58.1,9.53 57.15,10.48 57.15,17.78 46.99,27.94 v46.99,30.48
WF_IRQ  (via drill 0.3)
  Top 0.203: IC2.54 44.43,46.97 v46.99,49.53 | v13.34,60.96 v29.84,60.96 42.23,60.96 42.55,60.64 42.55,59.69 v43.5,58.74 v49.85,52.39 v51.44,50.8 v58.26,43.97 60.33,41.91 v60.33,30.48 v60.33,13.97 60.33,13.34 v60.33,10.79
  Bottom 0.203: v13.34,60.96 13.34,61.91 R30.1 13.34,62.55 13.34,66.19 Q3.2 | Q10.2 R44.1 68.89,8.89 66.99,10.79 v60.33,10.79 | v49.85,52.39 v46.99,49.53 | v29.84,60.96 29.84,61.91 R32.1 29.84,62.55 29.84,66.04 29.52,66.36 Q4.2 | v43.5,58.74 45.72,60.96 45.72,61.91 R34.1 46.35,62.55 46.35,66.04 46.03,66.36 Q5.2 | Q6.2 62.87,66.19 62.87,62.55 R36.1 62.55,61.91 v51.44,50.8 | Q7.2 65.55,46.99 61.91,46.99 R38.1 v58.26,43.97 | Q8.2 65.72,30.8 65.41,30.48 61.91,30.48 R40.1 61.27,30.48 v60.33,30.48 | Q9.2 65.72,14.29 65.41,13.97 61.91,13.97 | 61.91,13.97 R42.1 | v60.33,13.97 61.91,13.97
X1
  Top 0.203: IC3.34 30.32,7.14 32.07,5.4 34.61,5.4 35.63,4.38 Q2.1 35.92,4.45 C22.1
X2
  Top 0.203: IC3.33 29.82,4.74 R28.2

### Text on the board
tPlace: Tigers Mannheim | Base Station v1 | Freq: 2.4 - 2.525GHz | Designed by: A. Ryll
